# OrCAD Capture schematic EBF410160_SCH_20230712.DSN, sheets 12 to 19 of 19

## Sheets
12 16 MIPI CSI PORT: size A4; note: MIPI CSI PORT
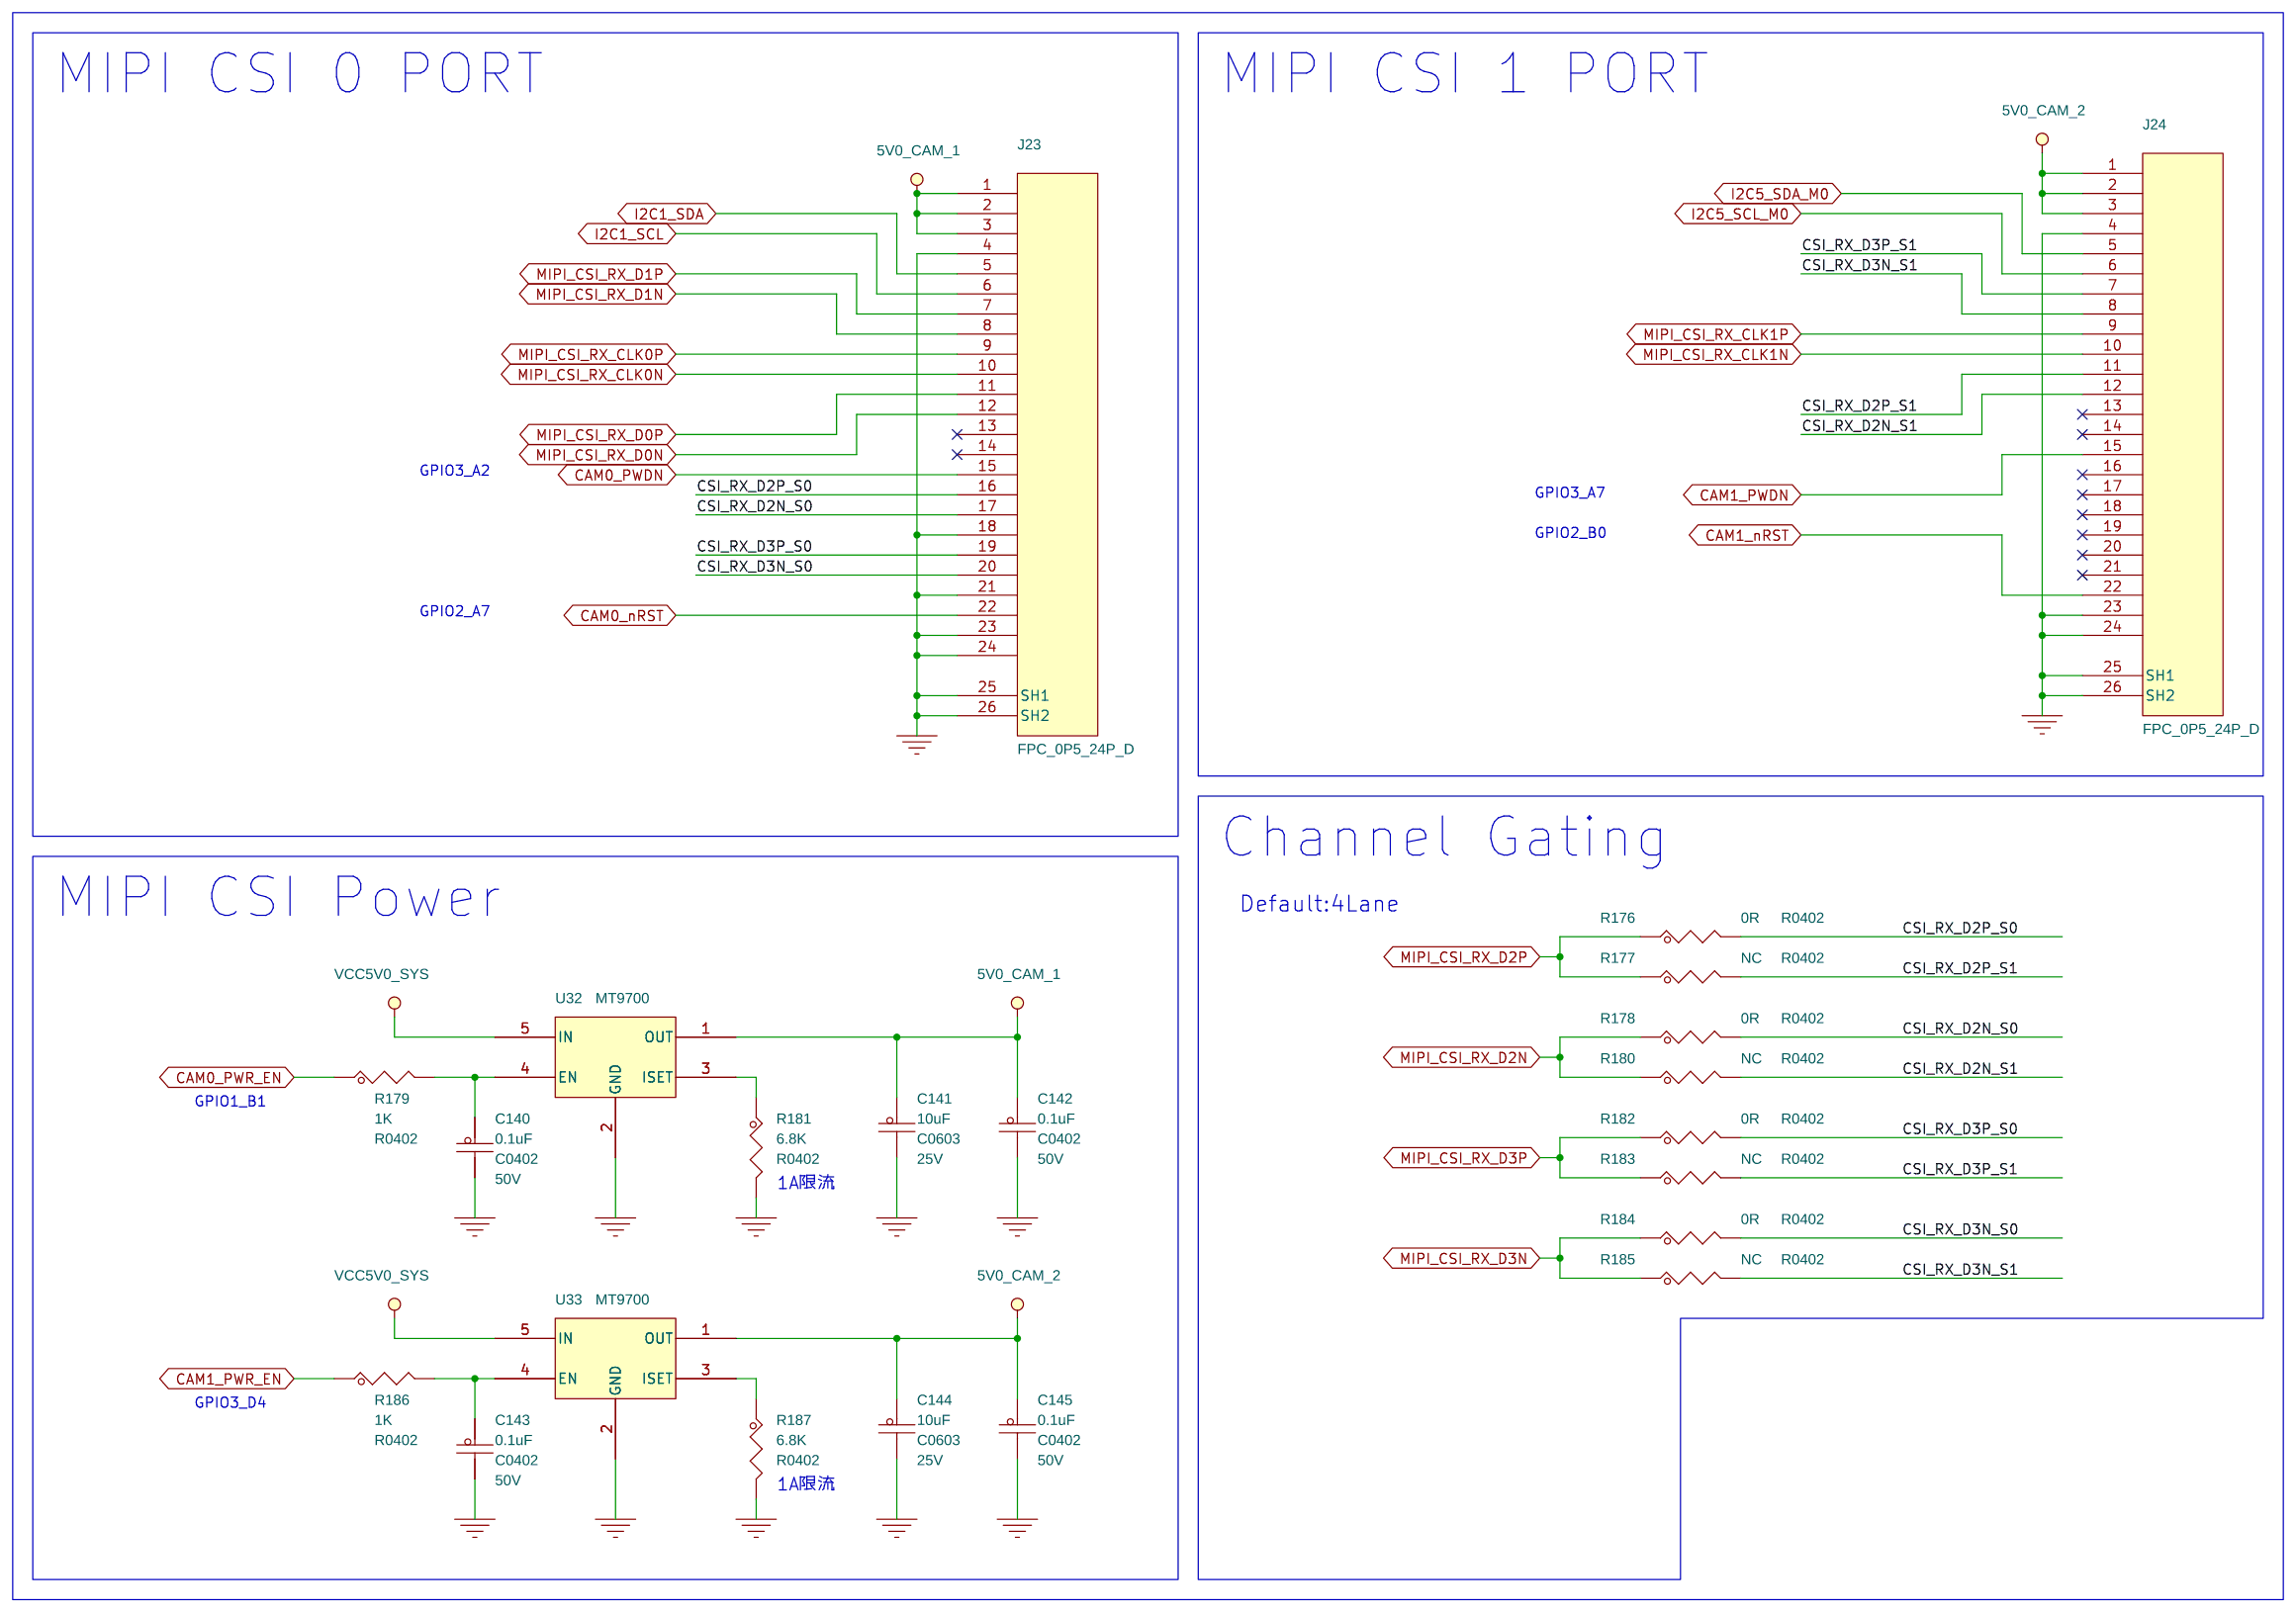
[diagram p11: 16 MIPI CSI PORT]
13 18 MINI PCIE_PORT: size A3; note: MINI PCIE PORT
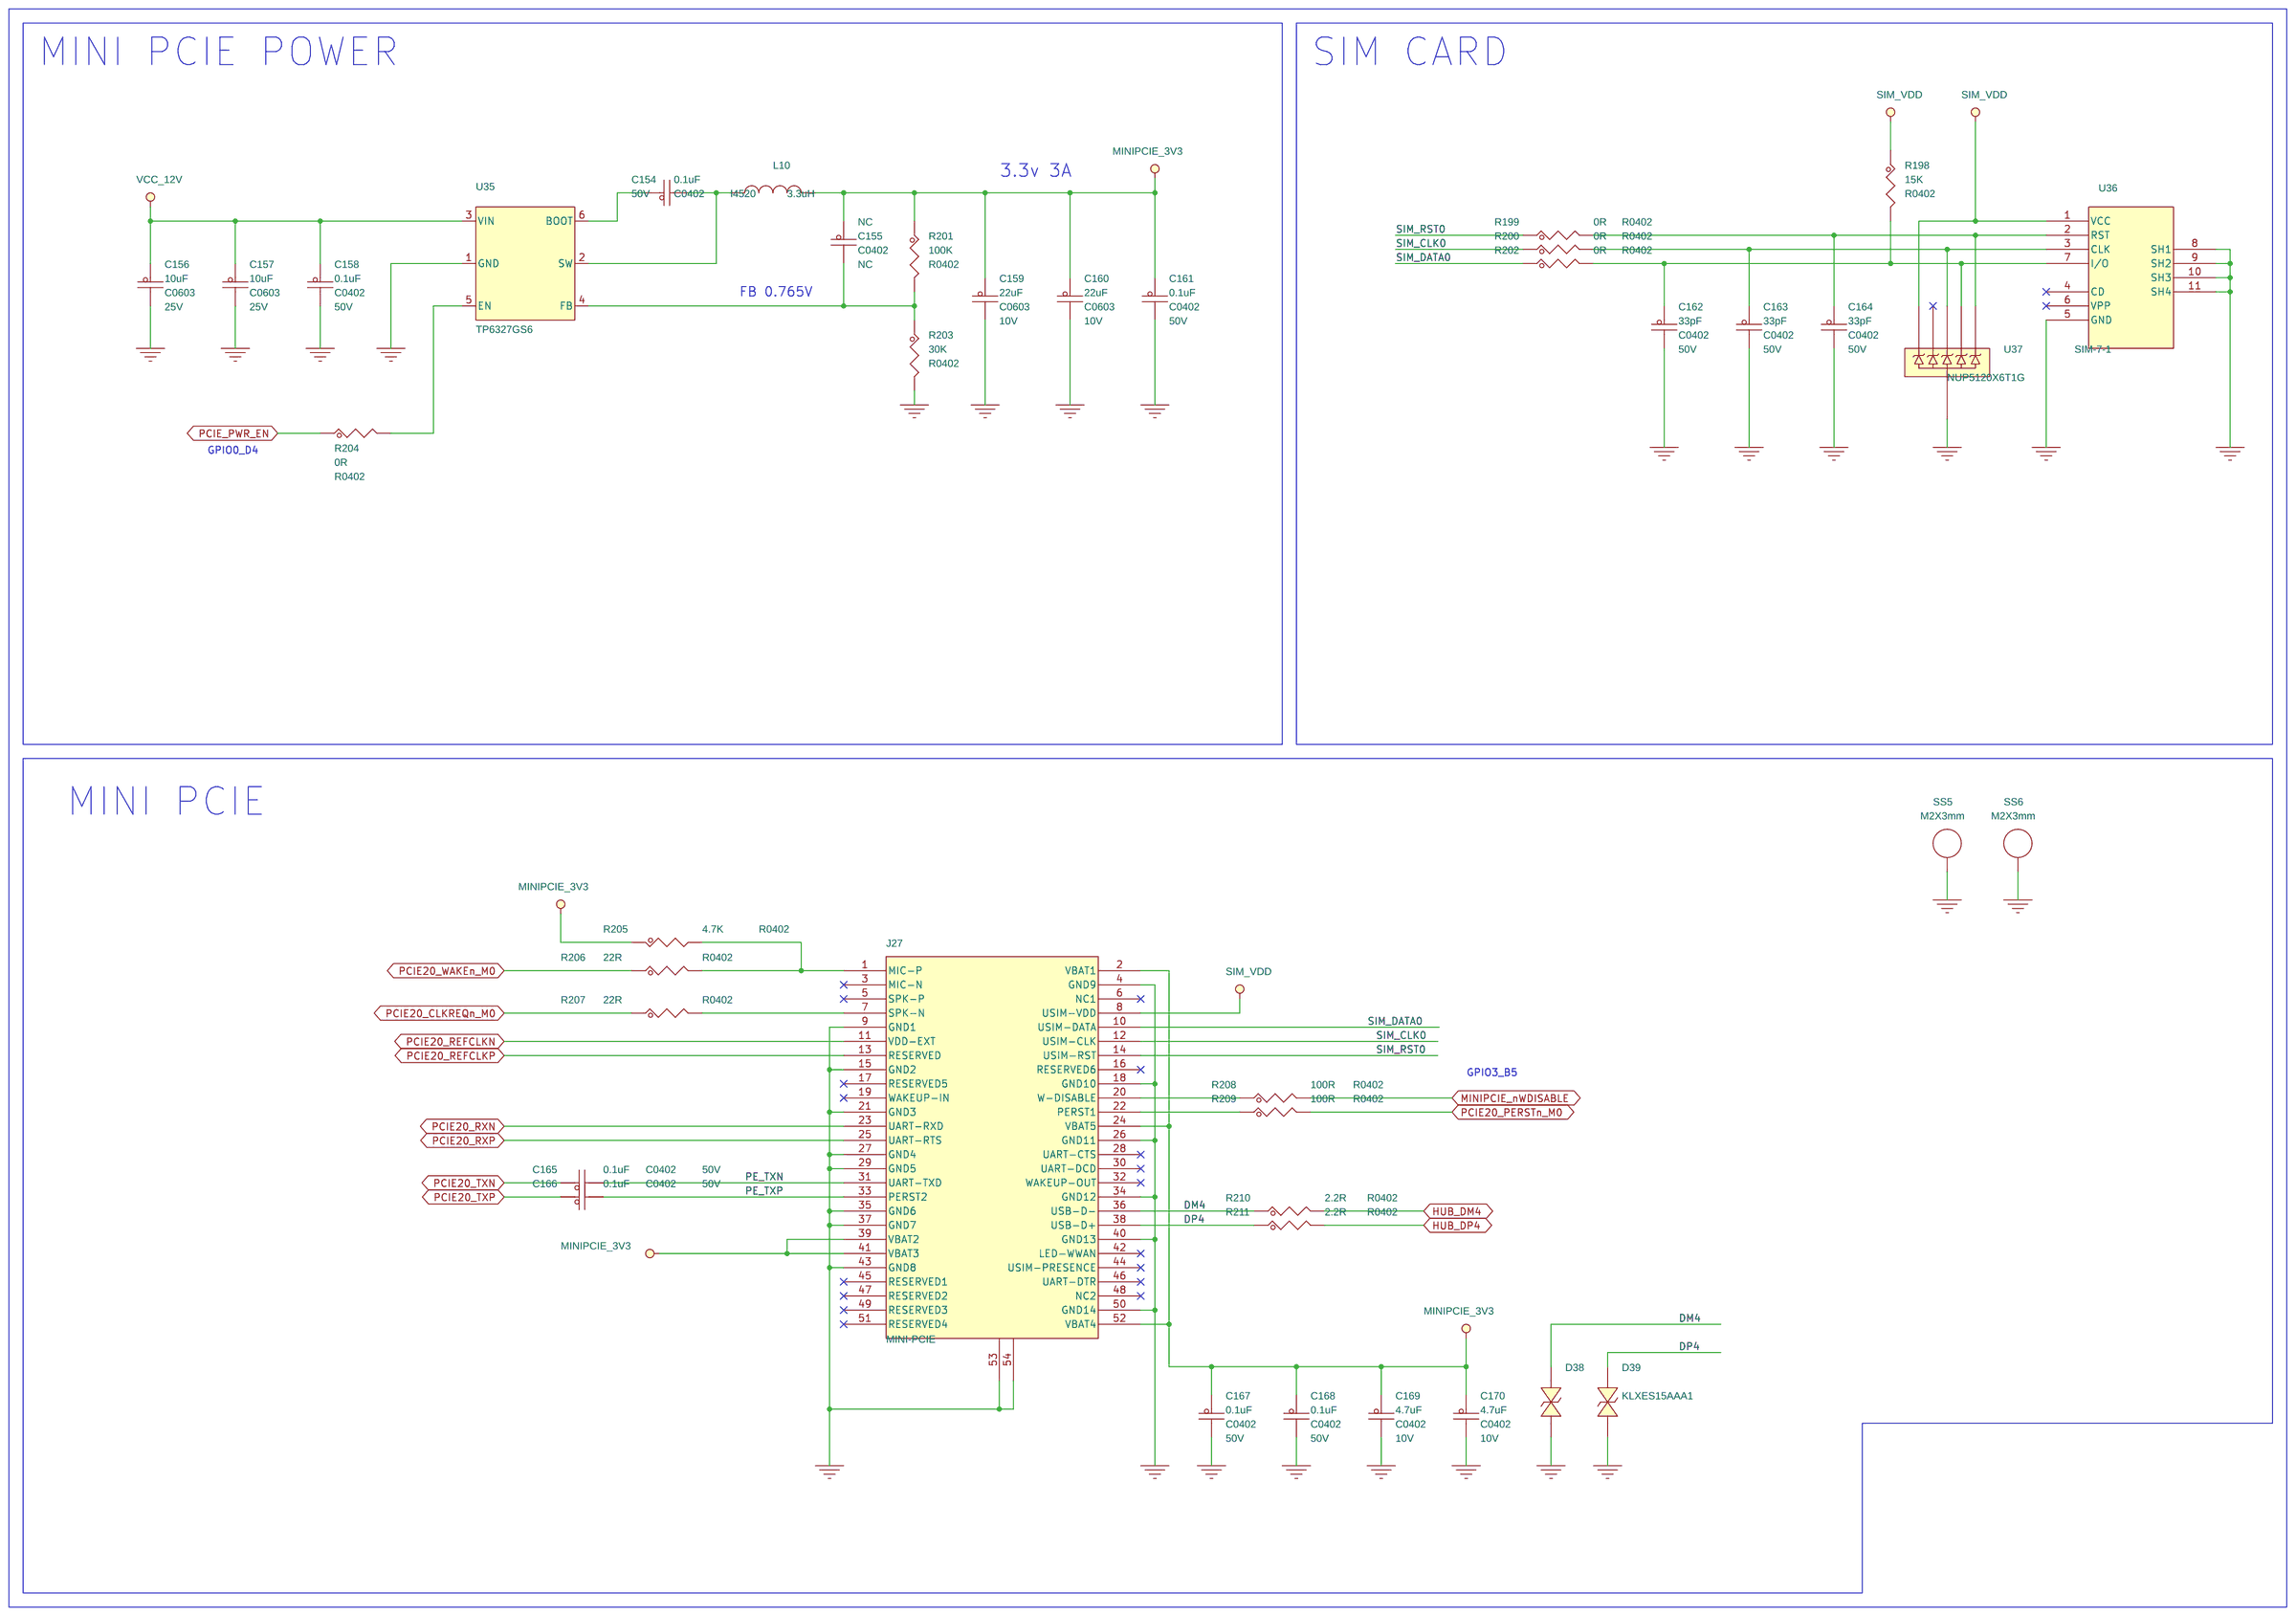
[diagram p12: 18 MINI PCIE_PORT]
14 19 AUDIO PORT: size A4; note: AUDIO PORT
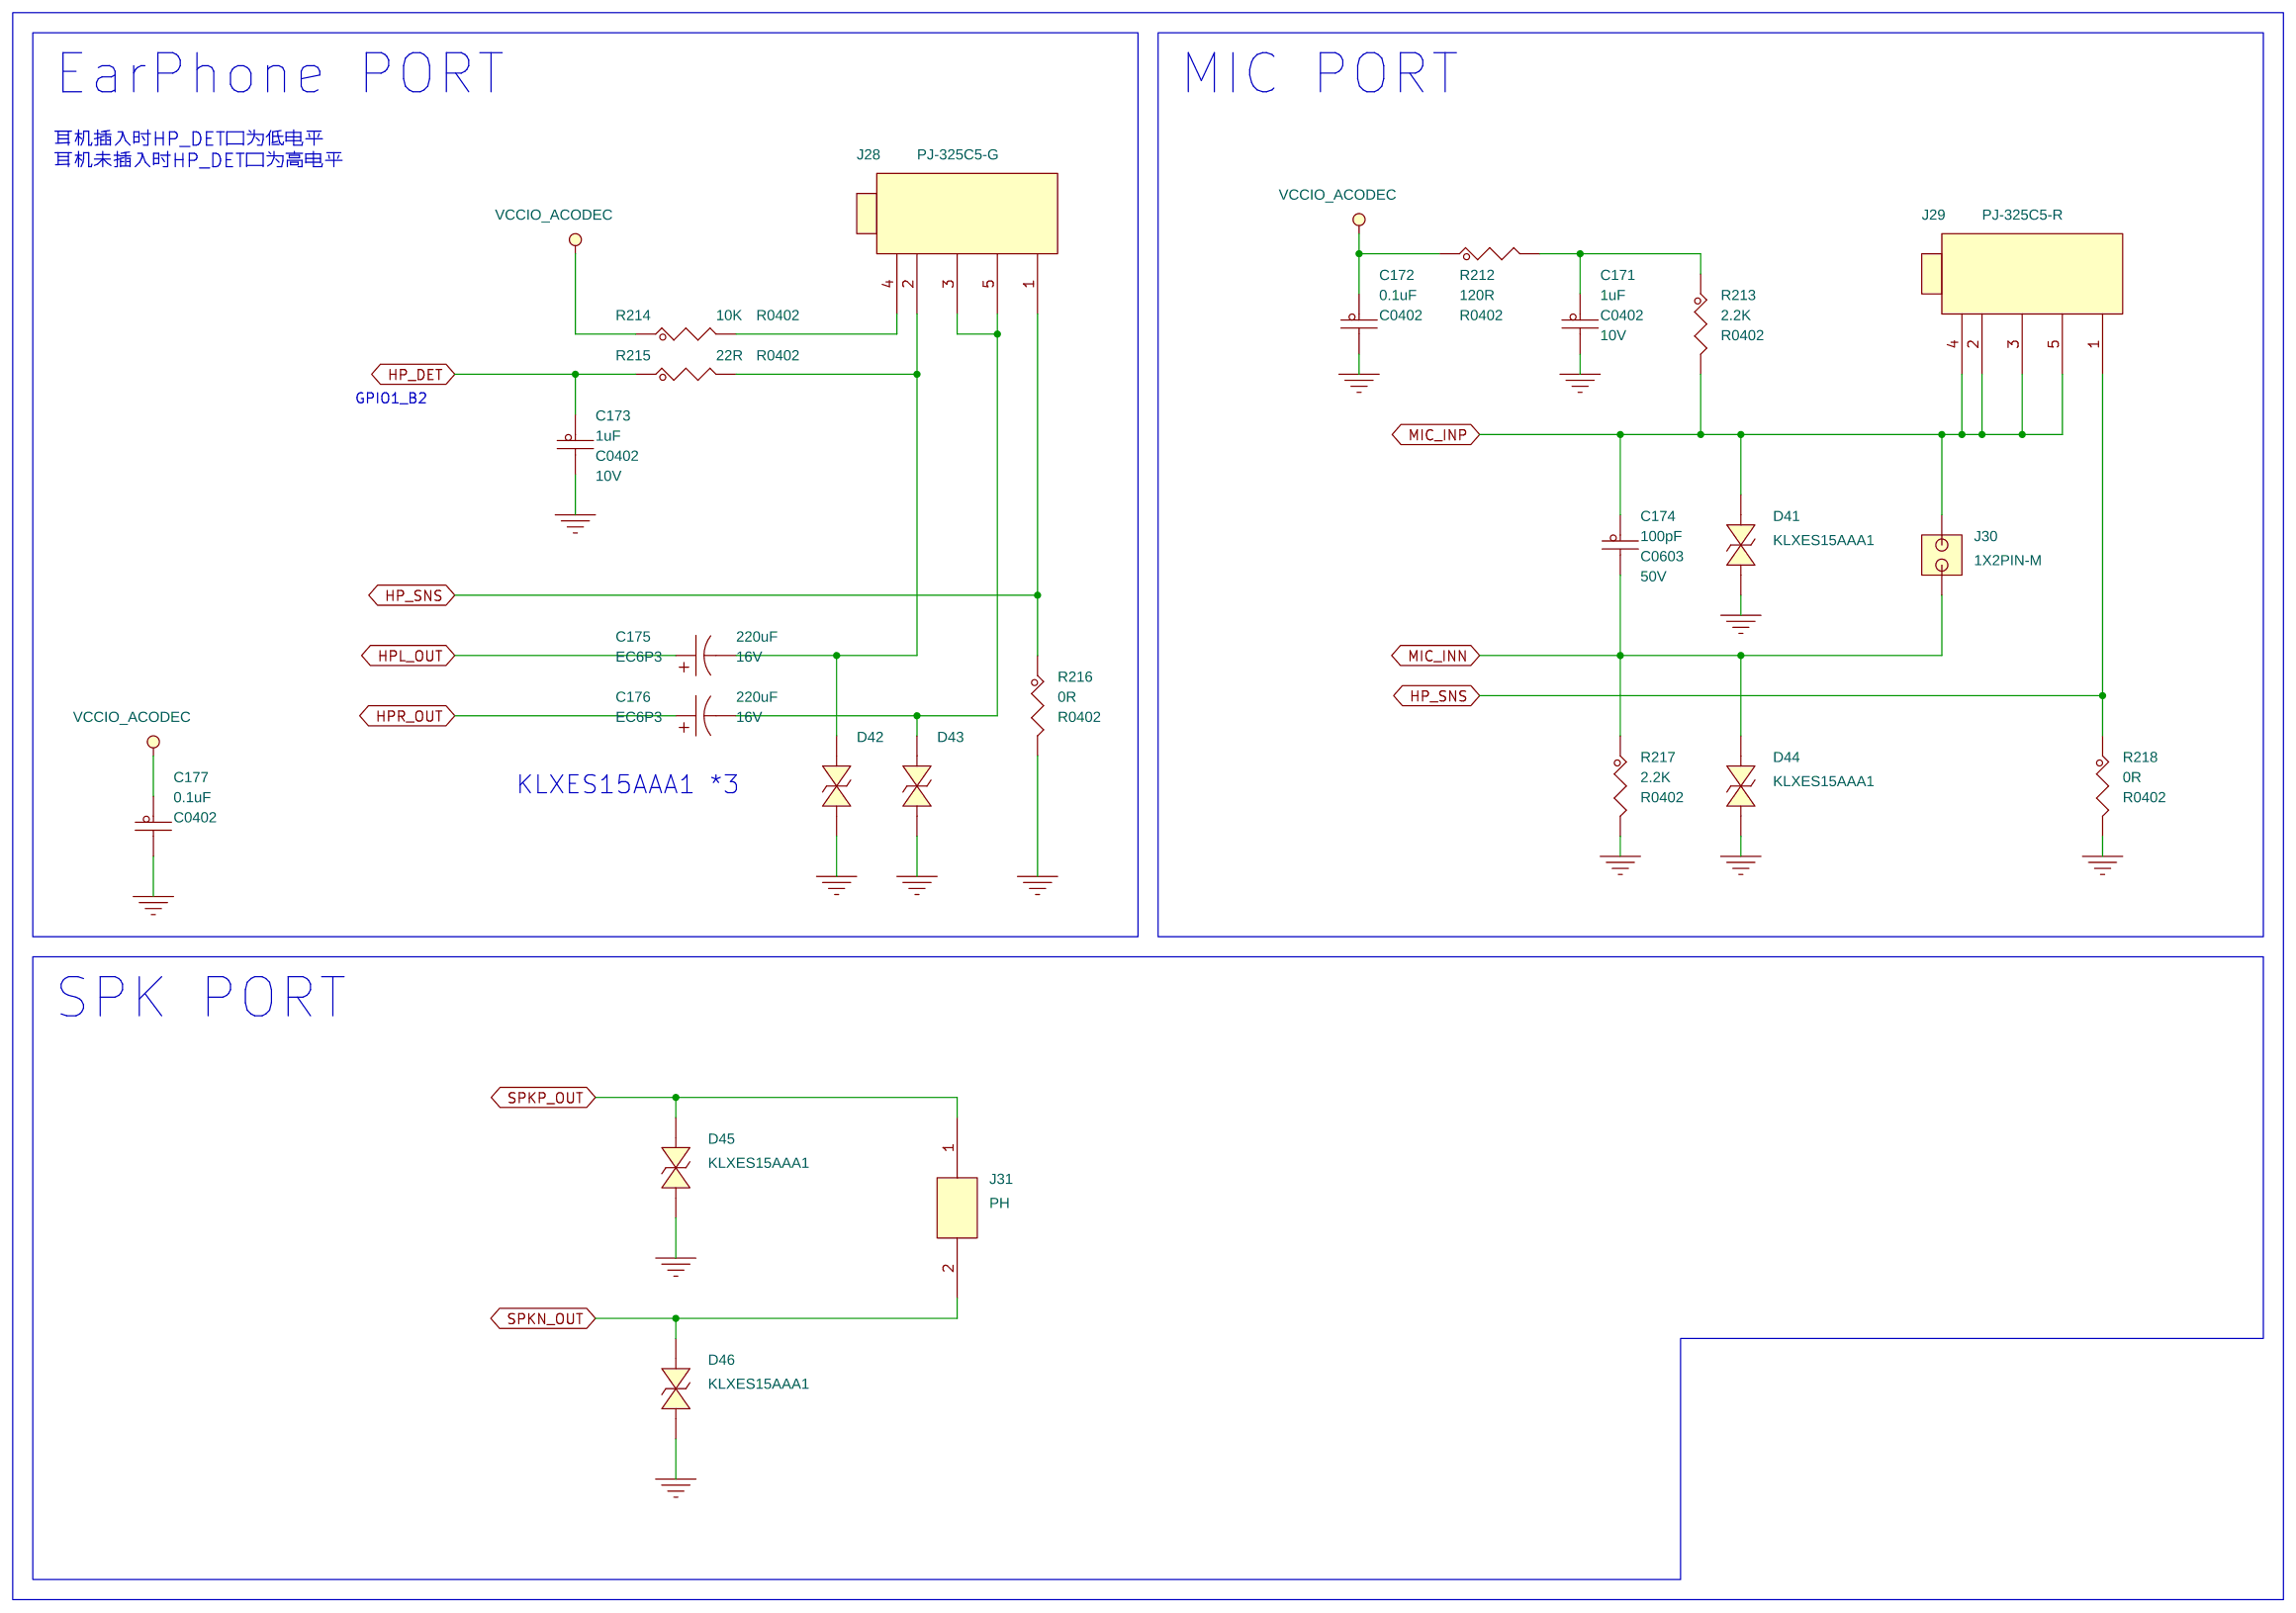
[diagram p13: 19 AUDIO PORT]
15 08 SD/RTC/RS232: size A3; note: SD/RTC/RS232
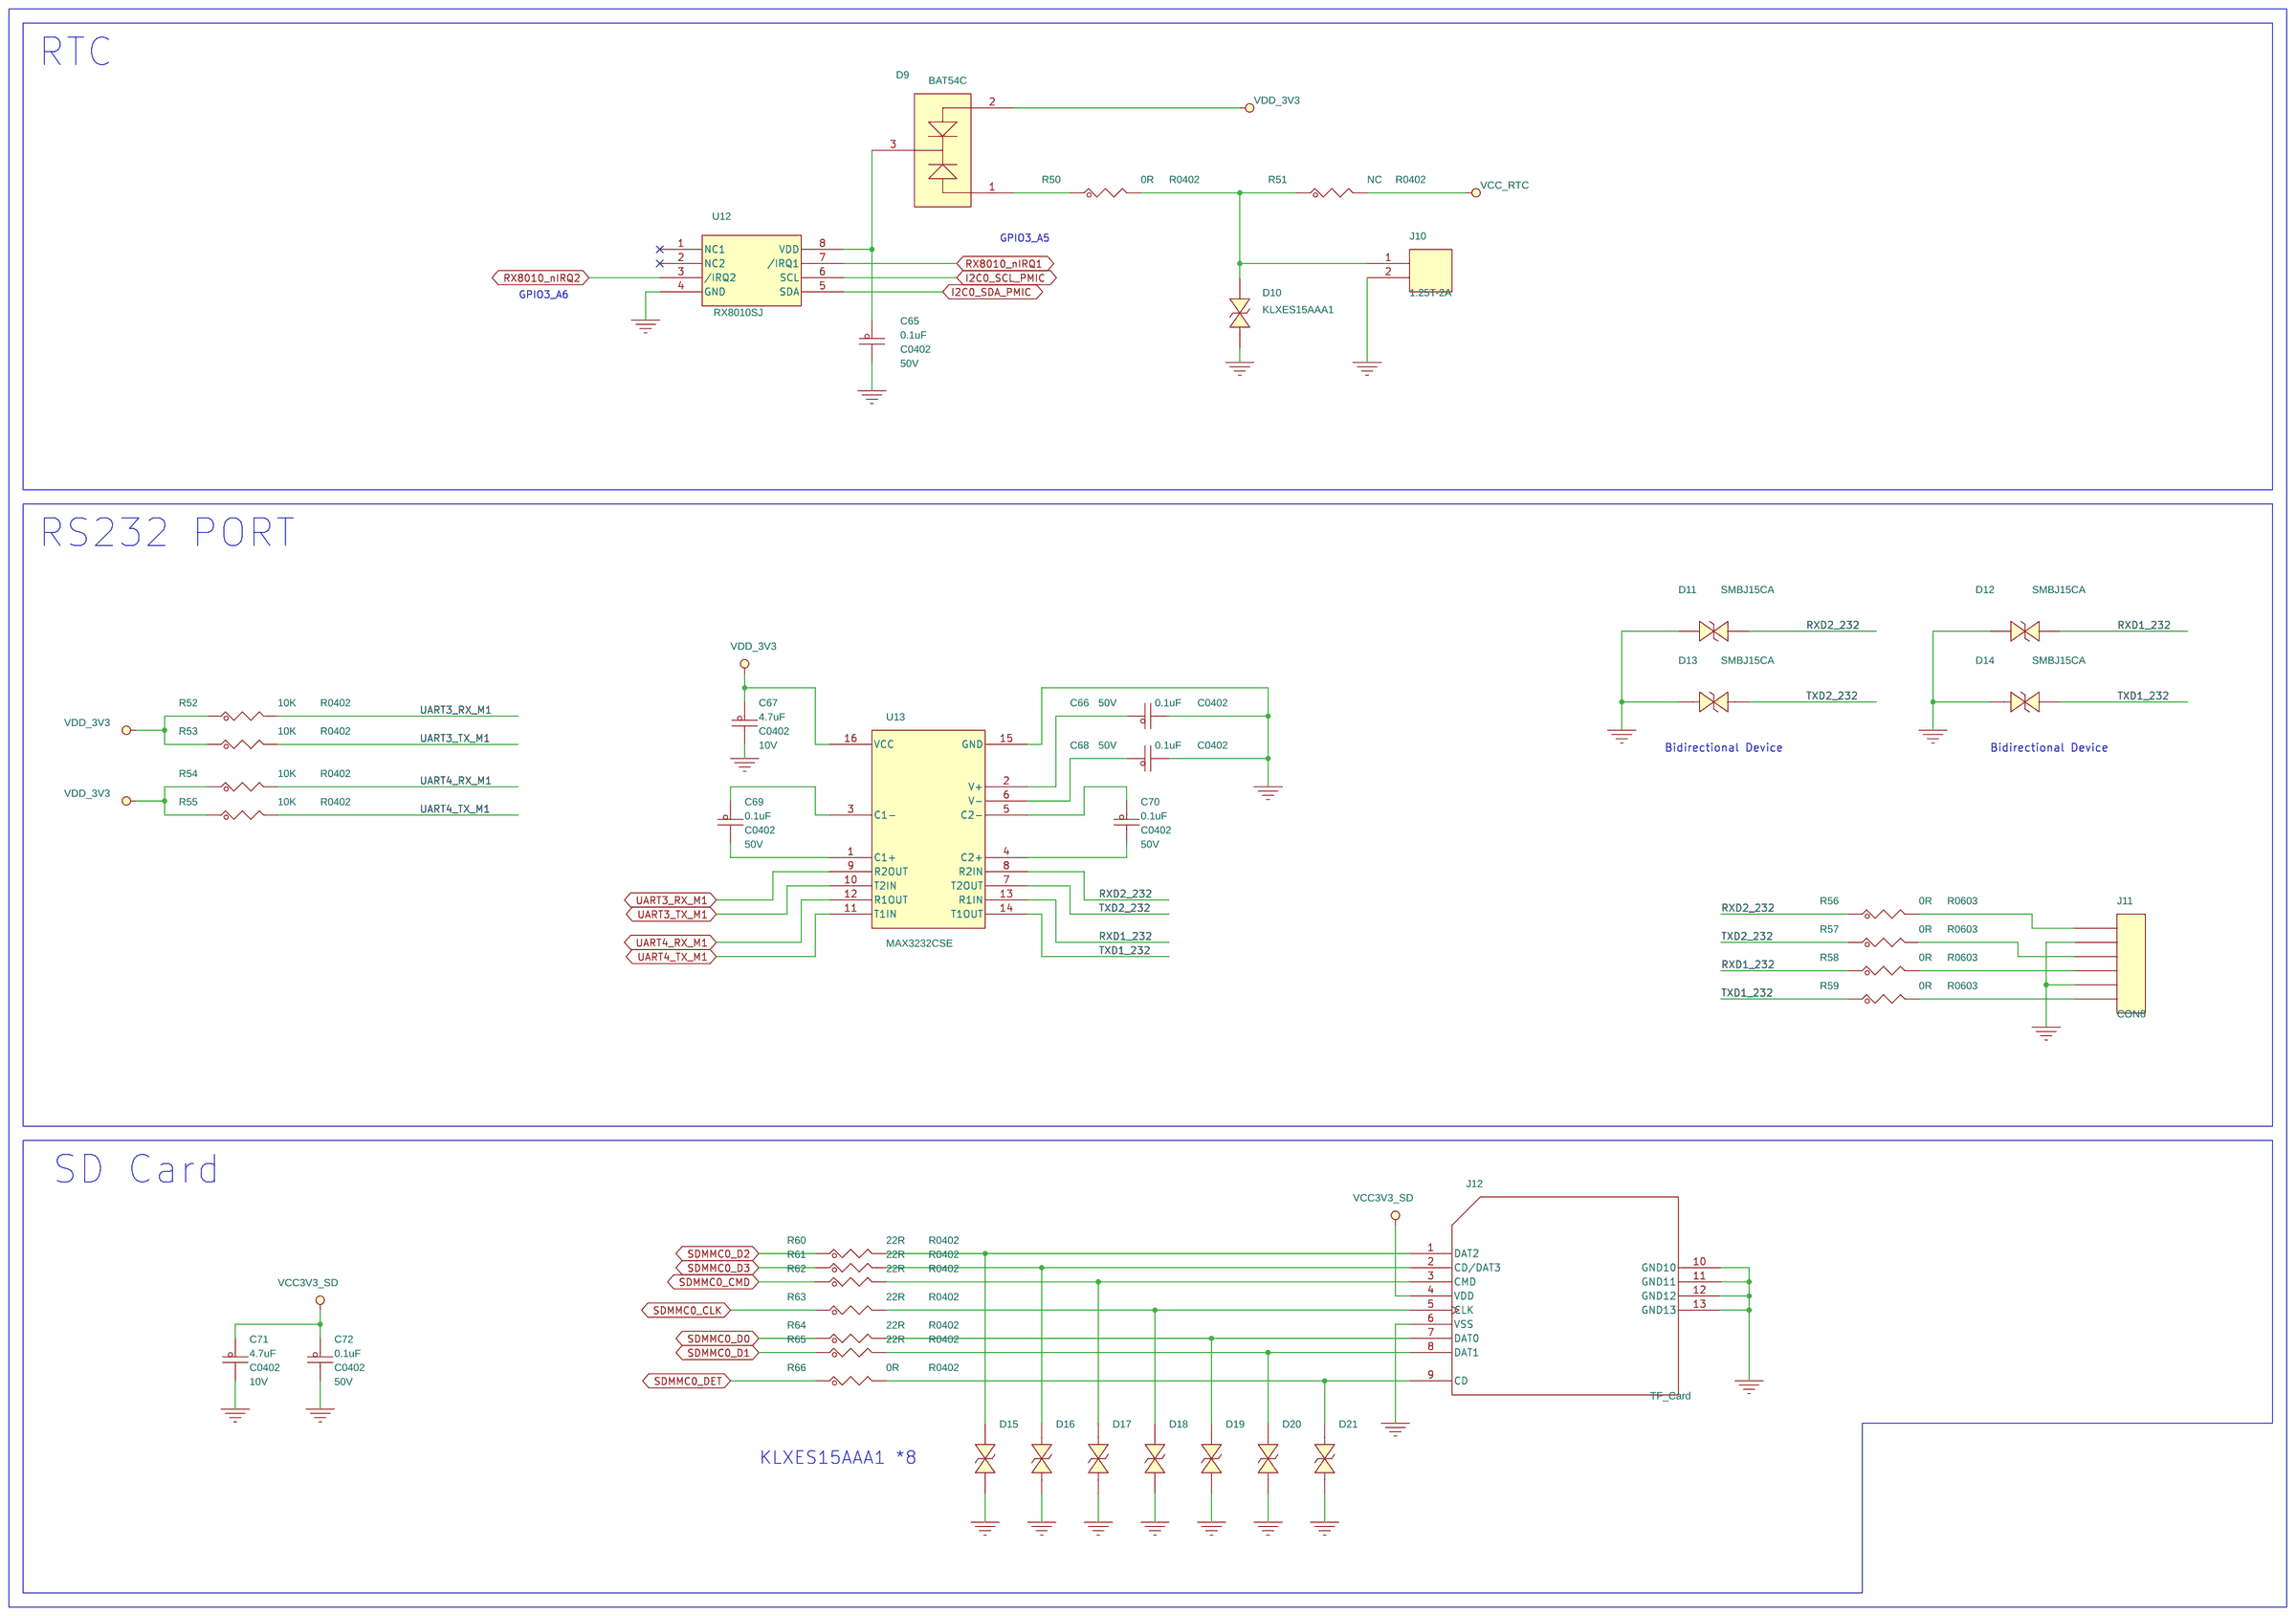
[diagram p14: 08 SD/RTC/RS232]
16 10 I2C/UART PORT: size A4; note: 40P  GPIO
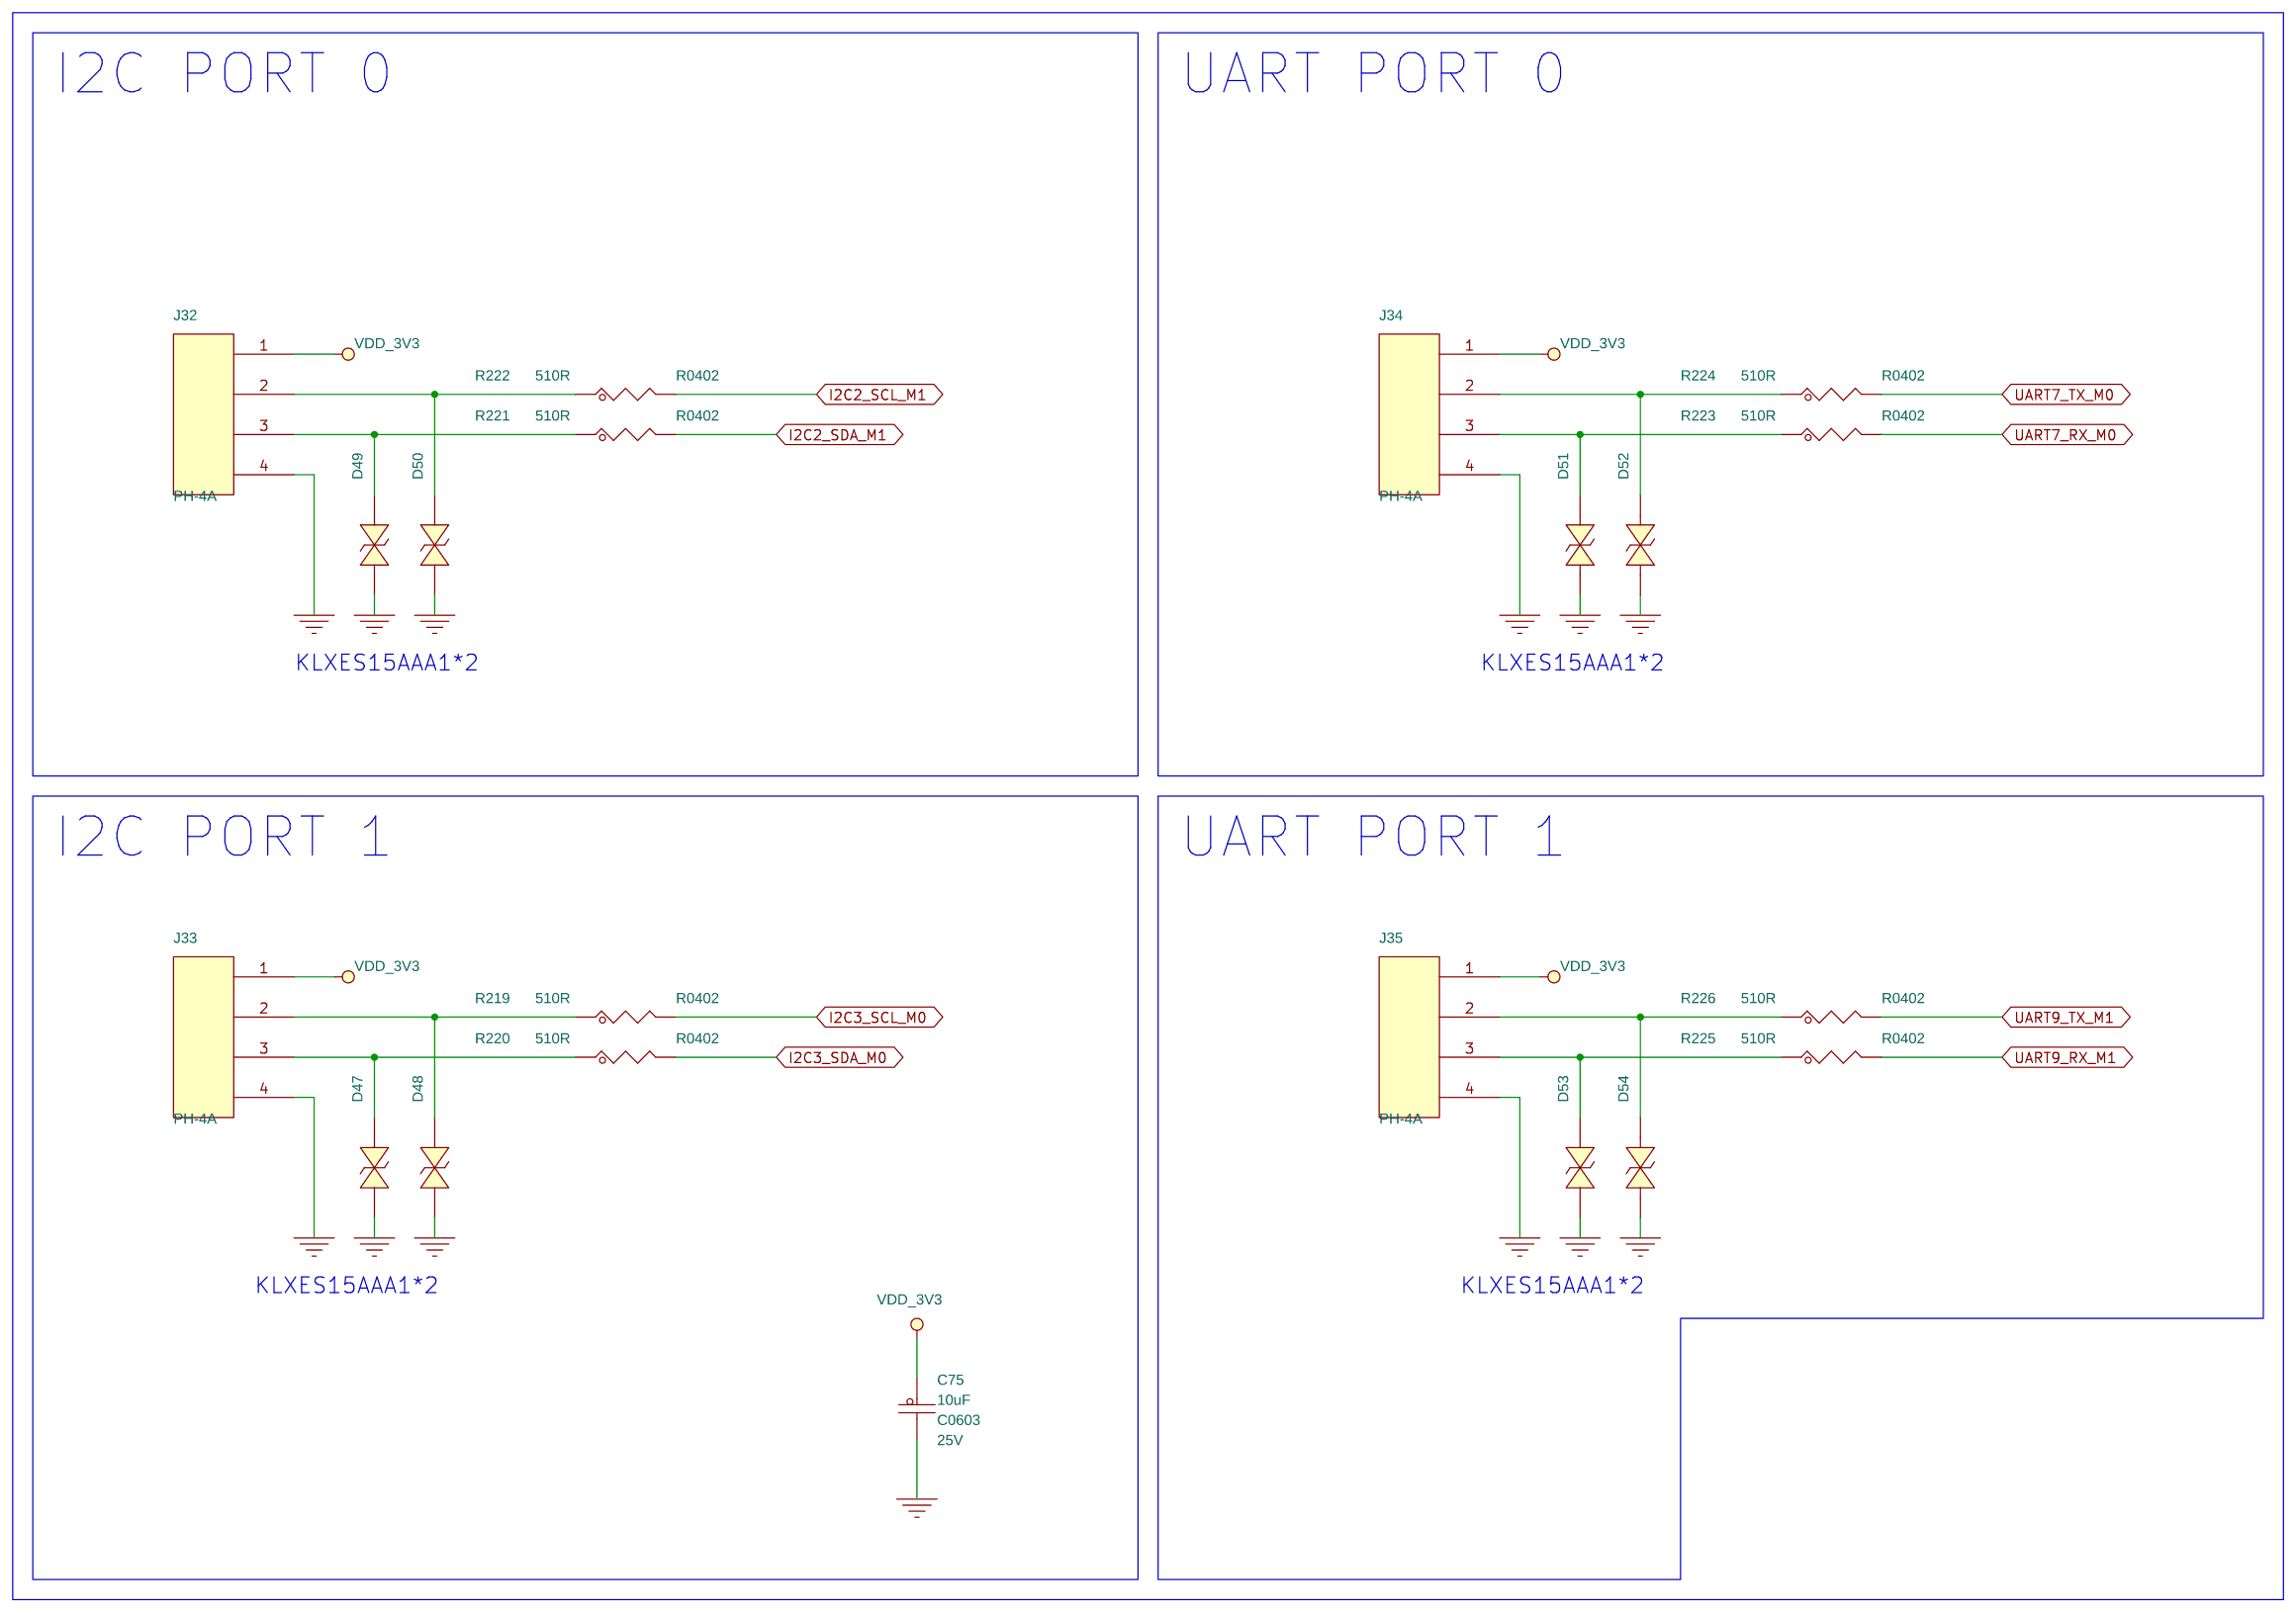
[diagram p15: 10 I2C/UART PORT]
17 04 DC IN/POWER/FAN: size A3; note: DC IN/POWER/FAN
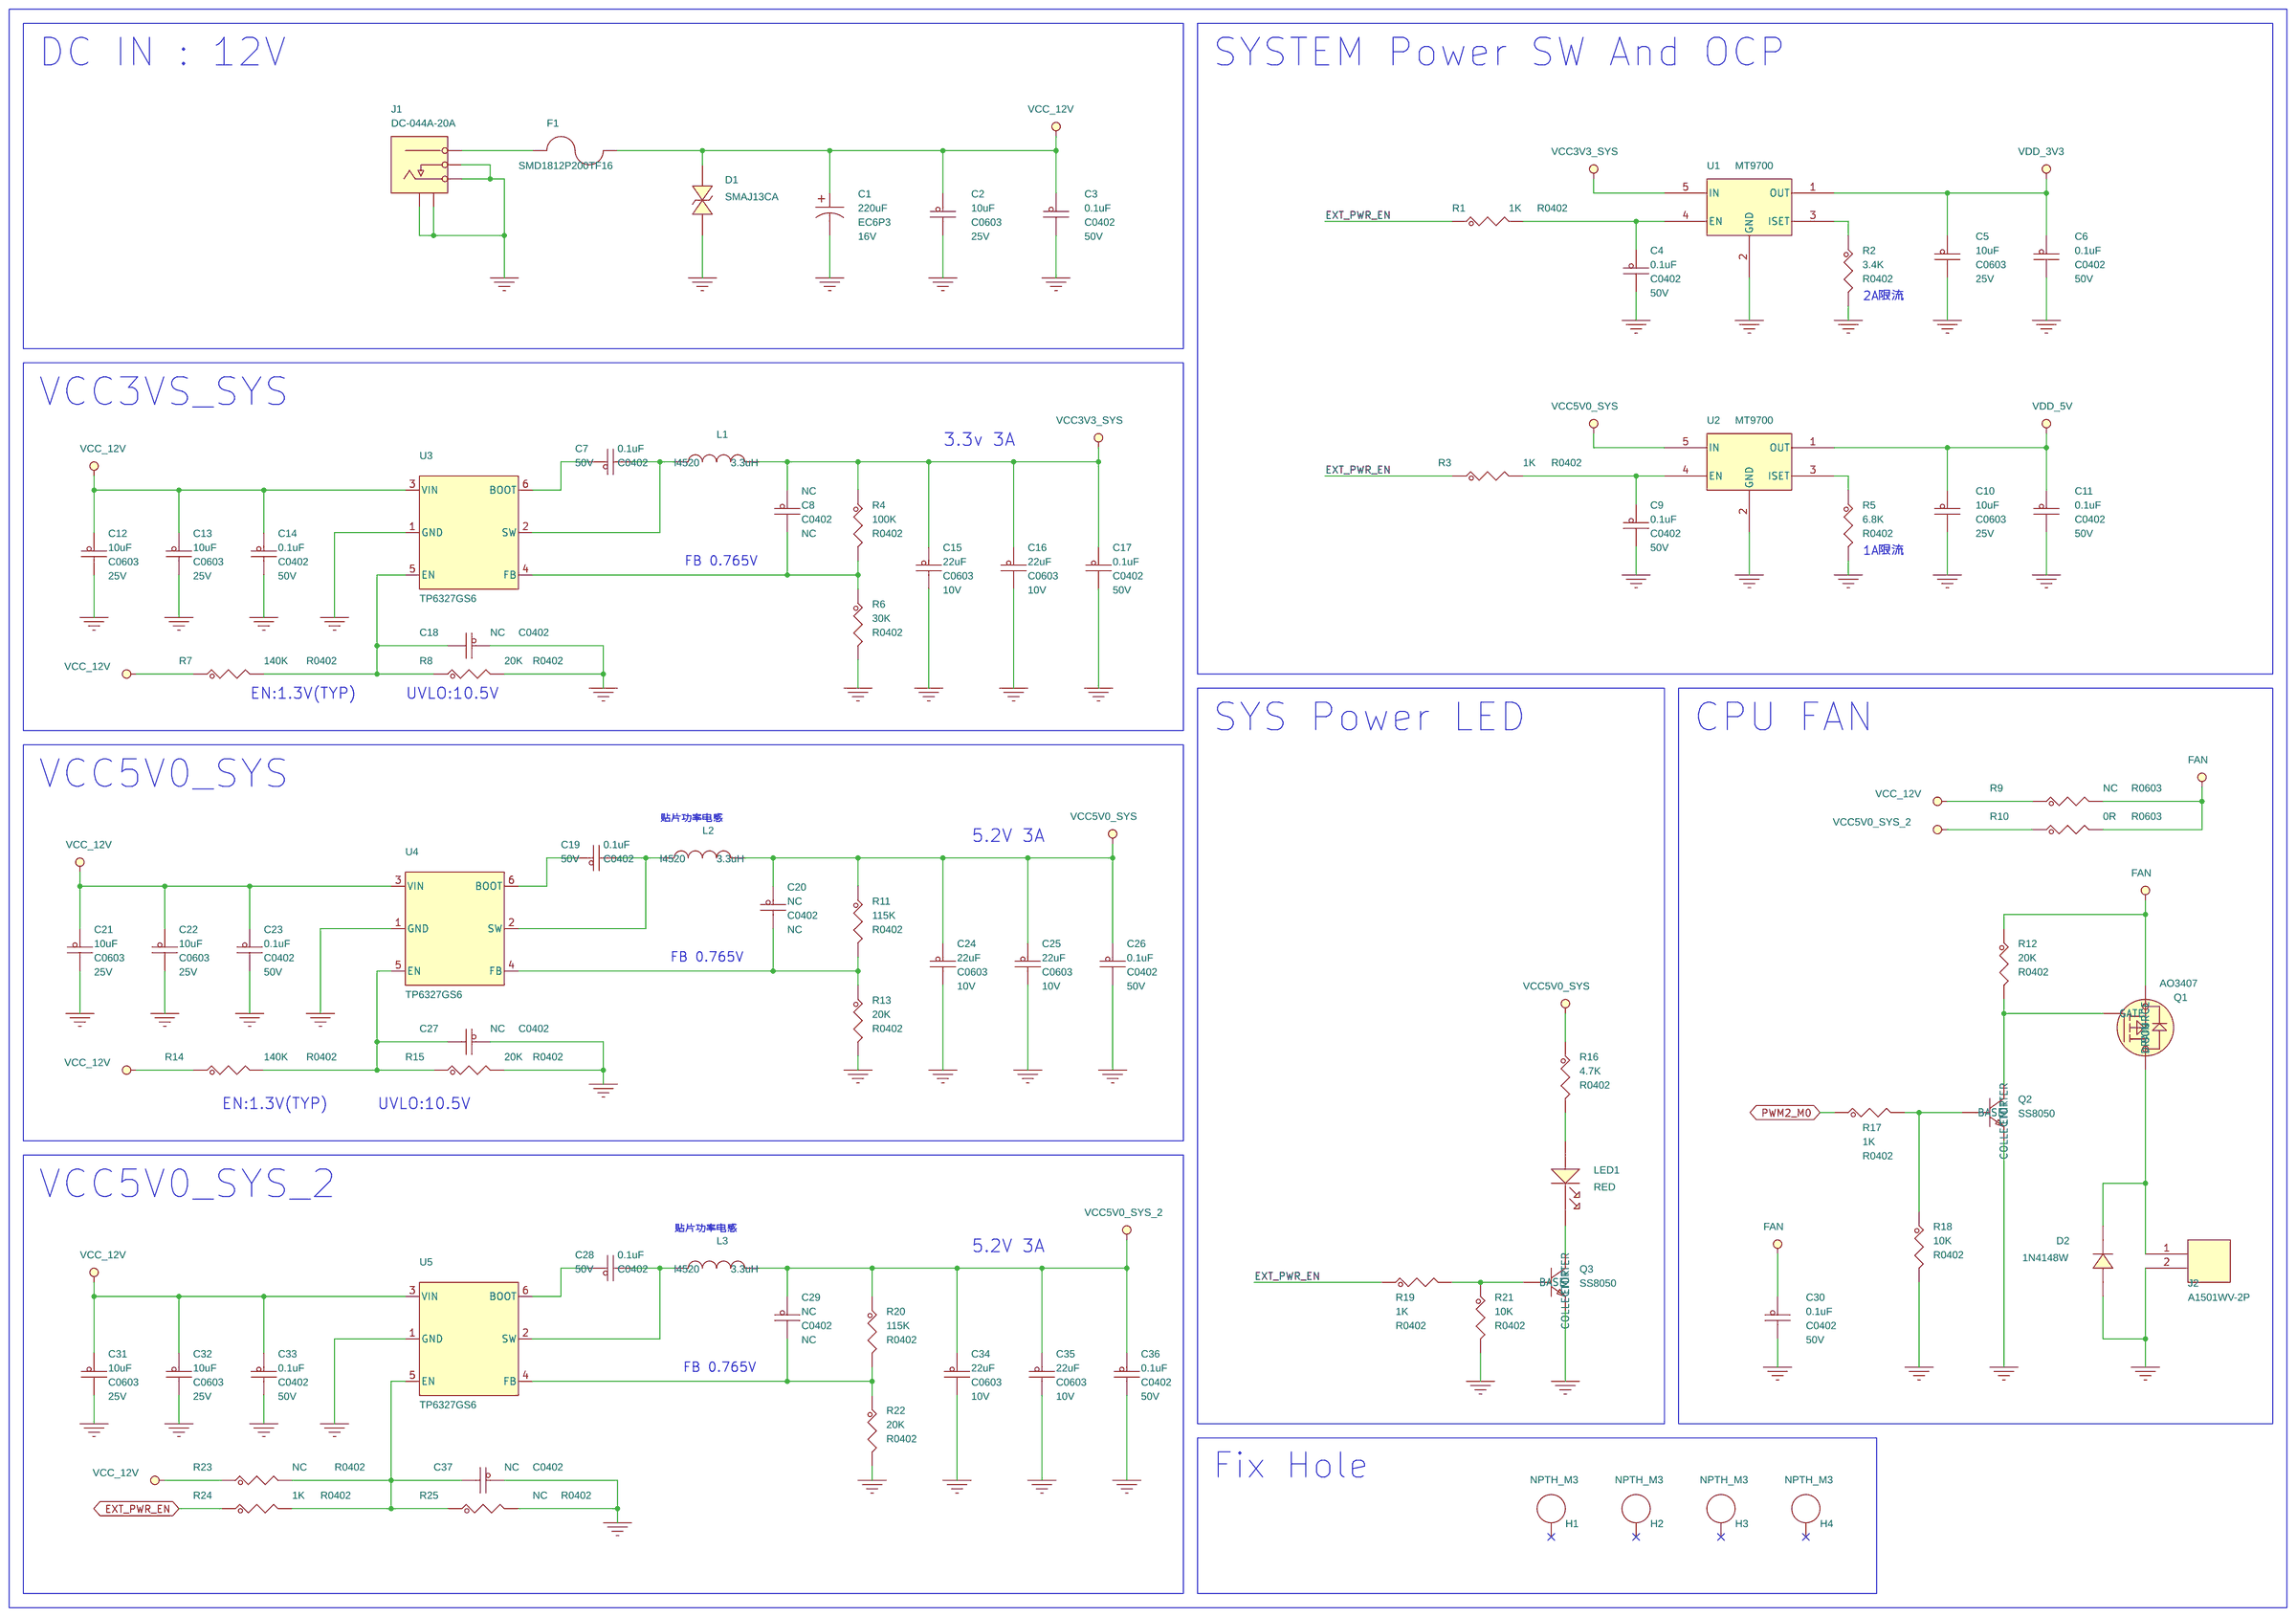
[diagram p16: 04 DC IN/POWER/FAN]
18 17 eDP_1.3/TP_PORT: size A4; note: eDP1.3/TP_PORT
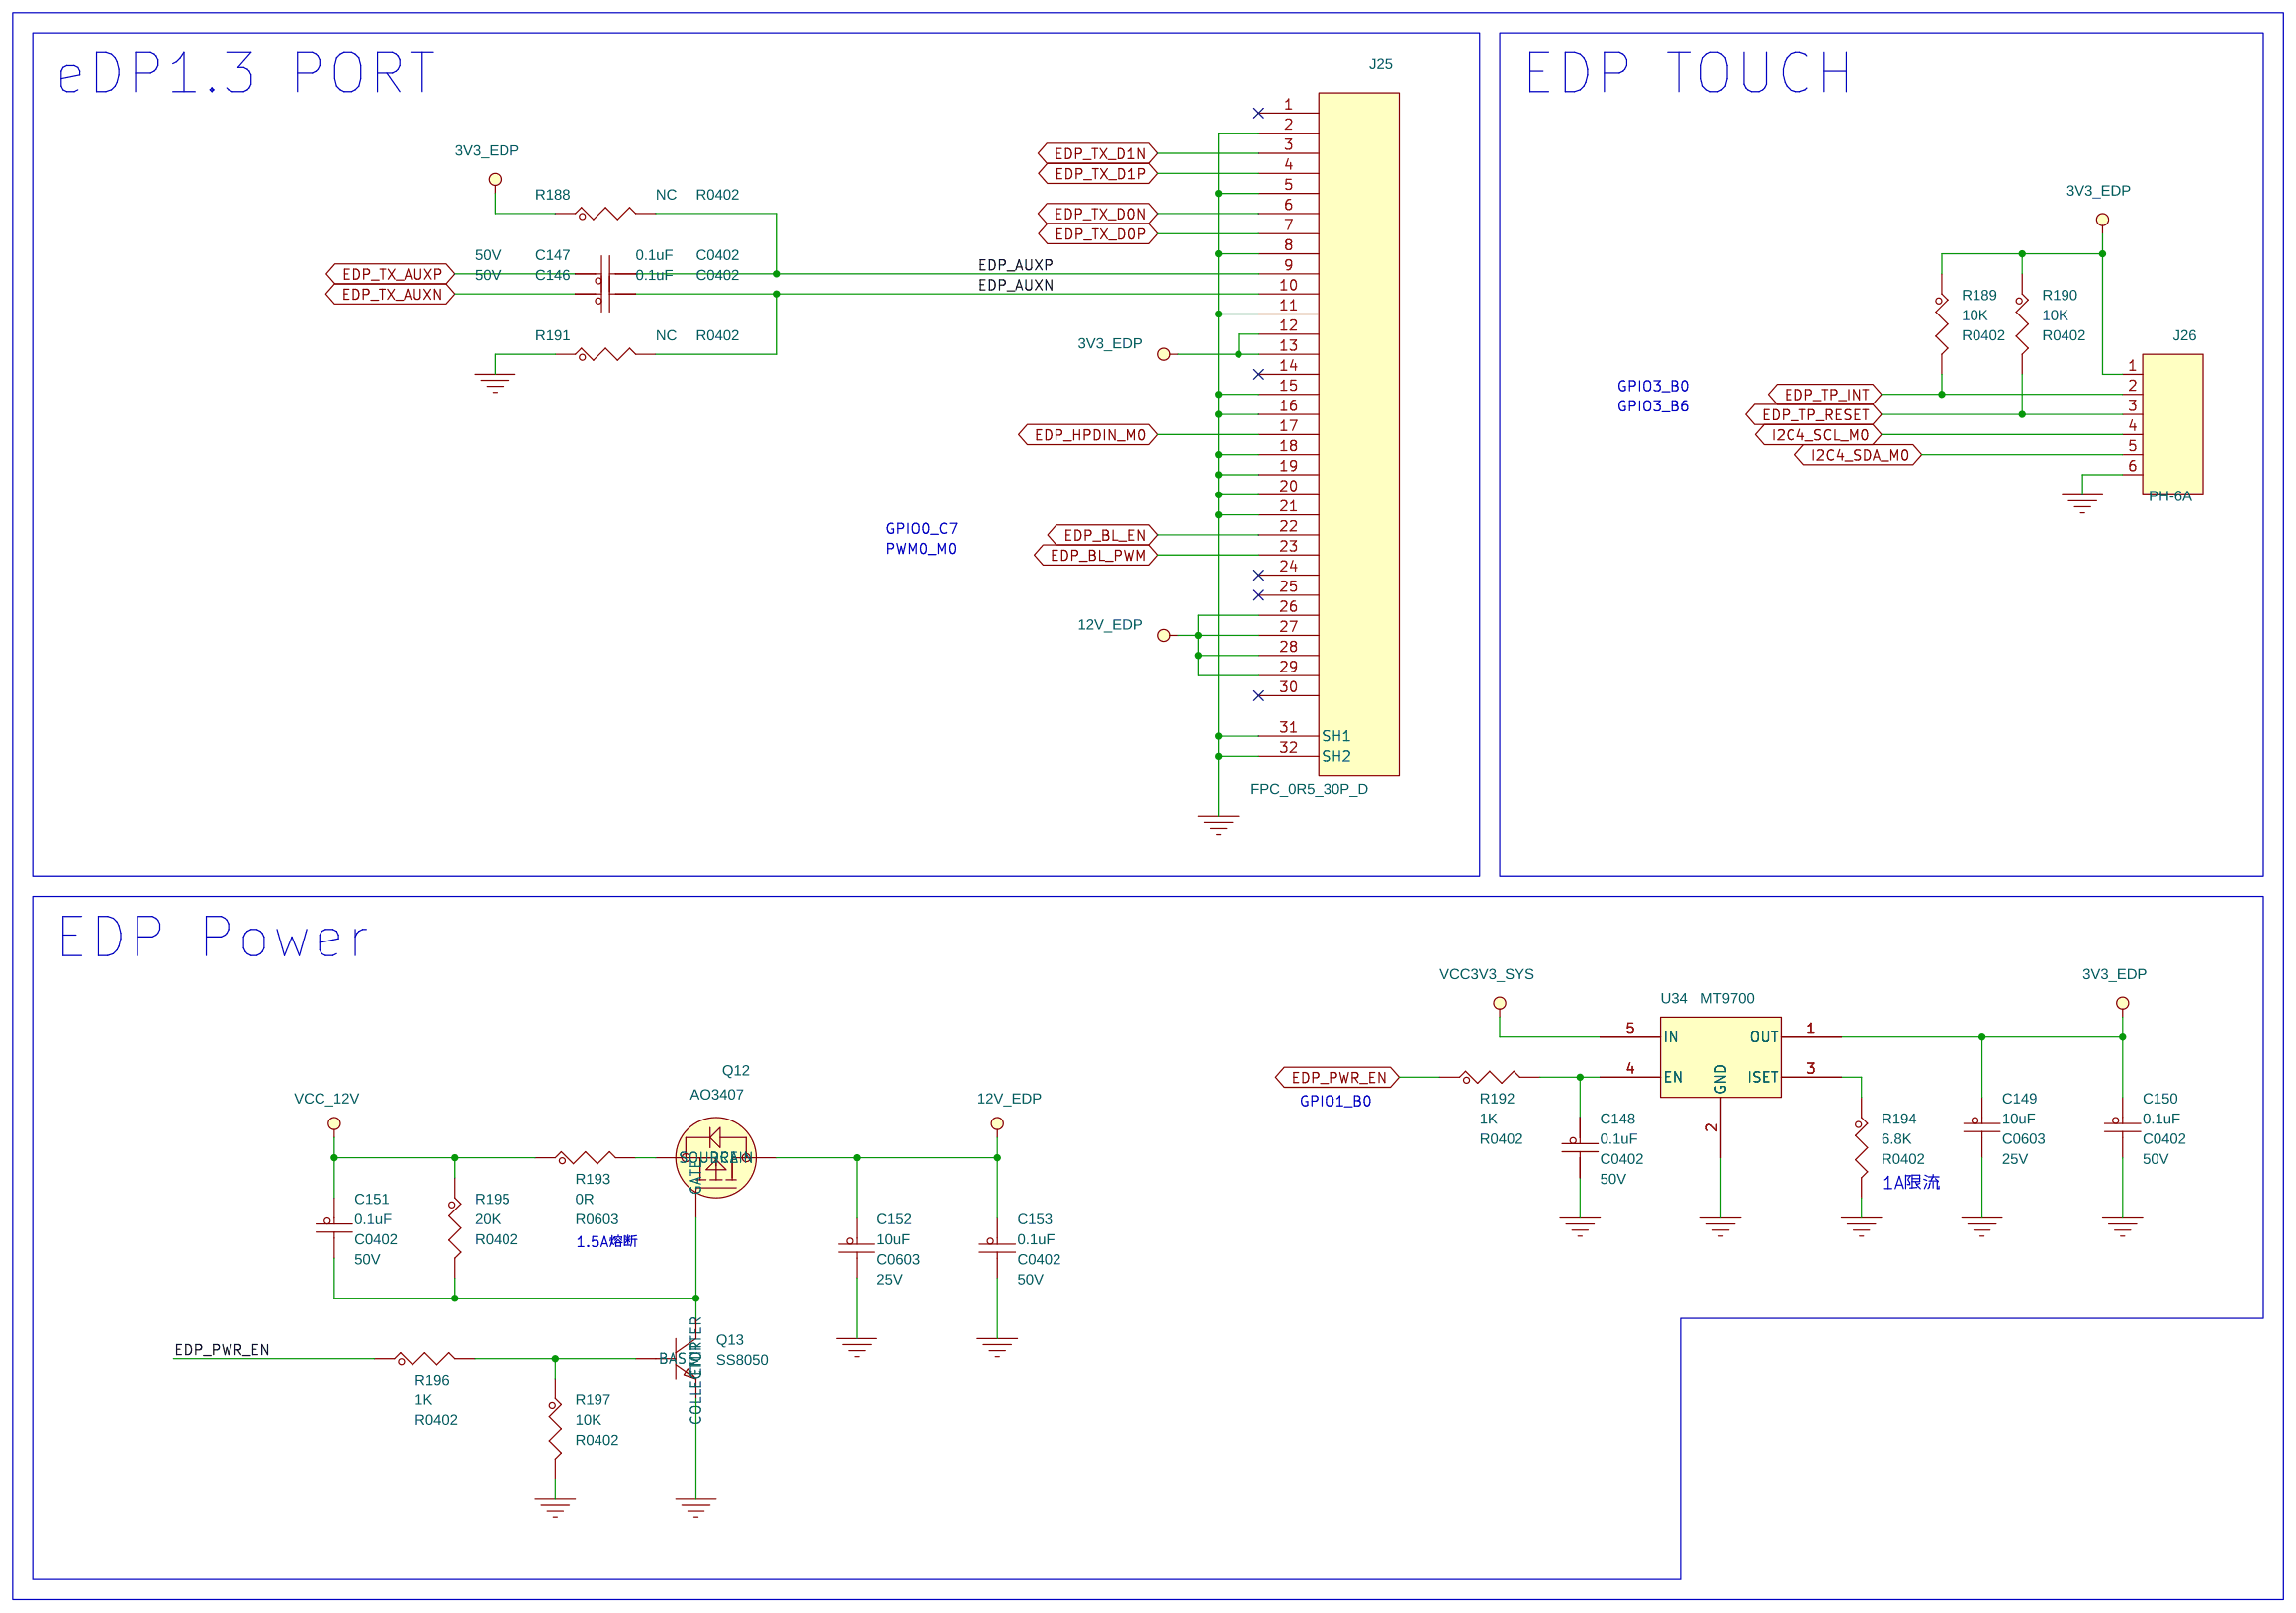
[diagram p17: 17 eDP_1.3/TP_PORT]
19 07 Button/FLASH/IR/DEBUG/LED: size A3; note: Button/FLASH/IR/DEBUG/LED
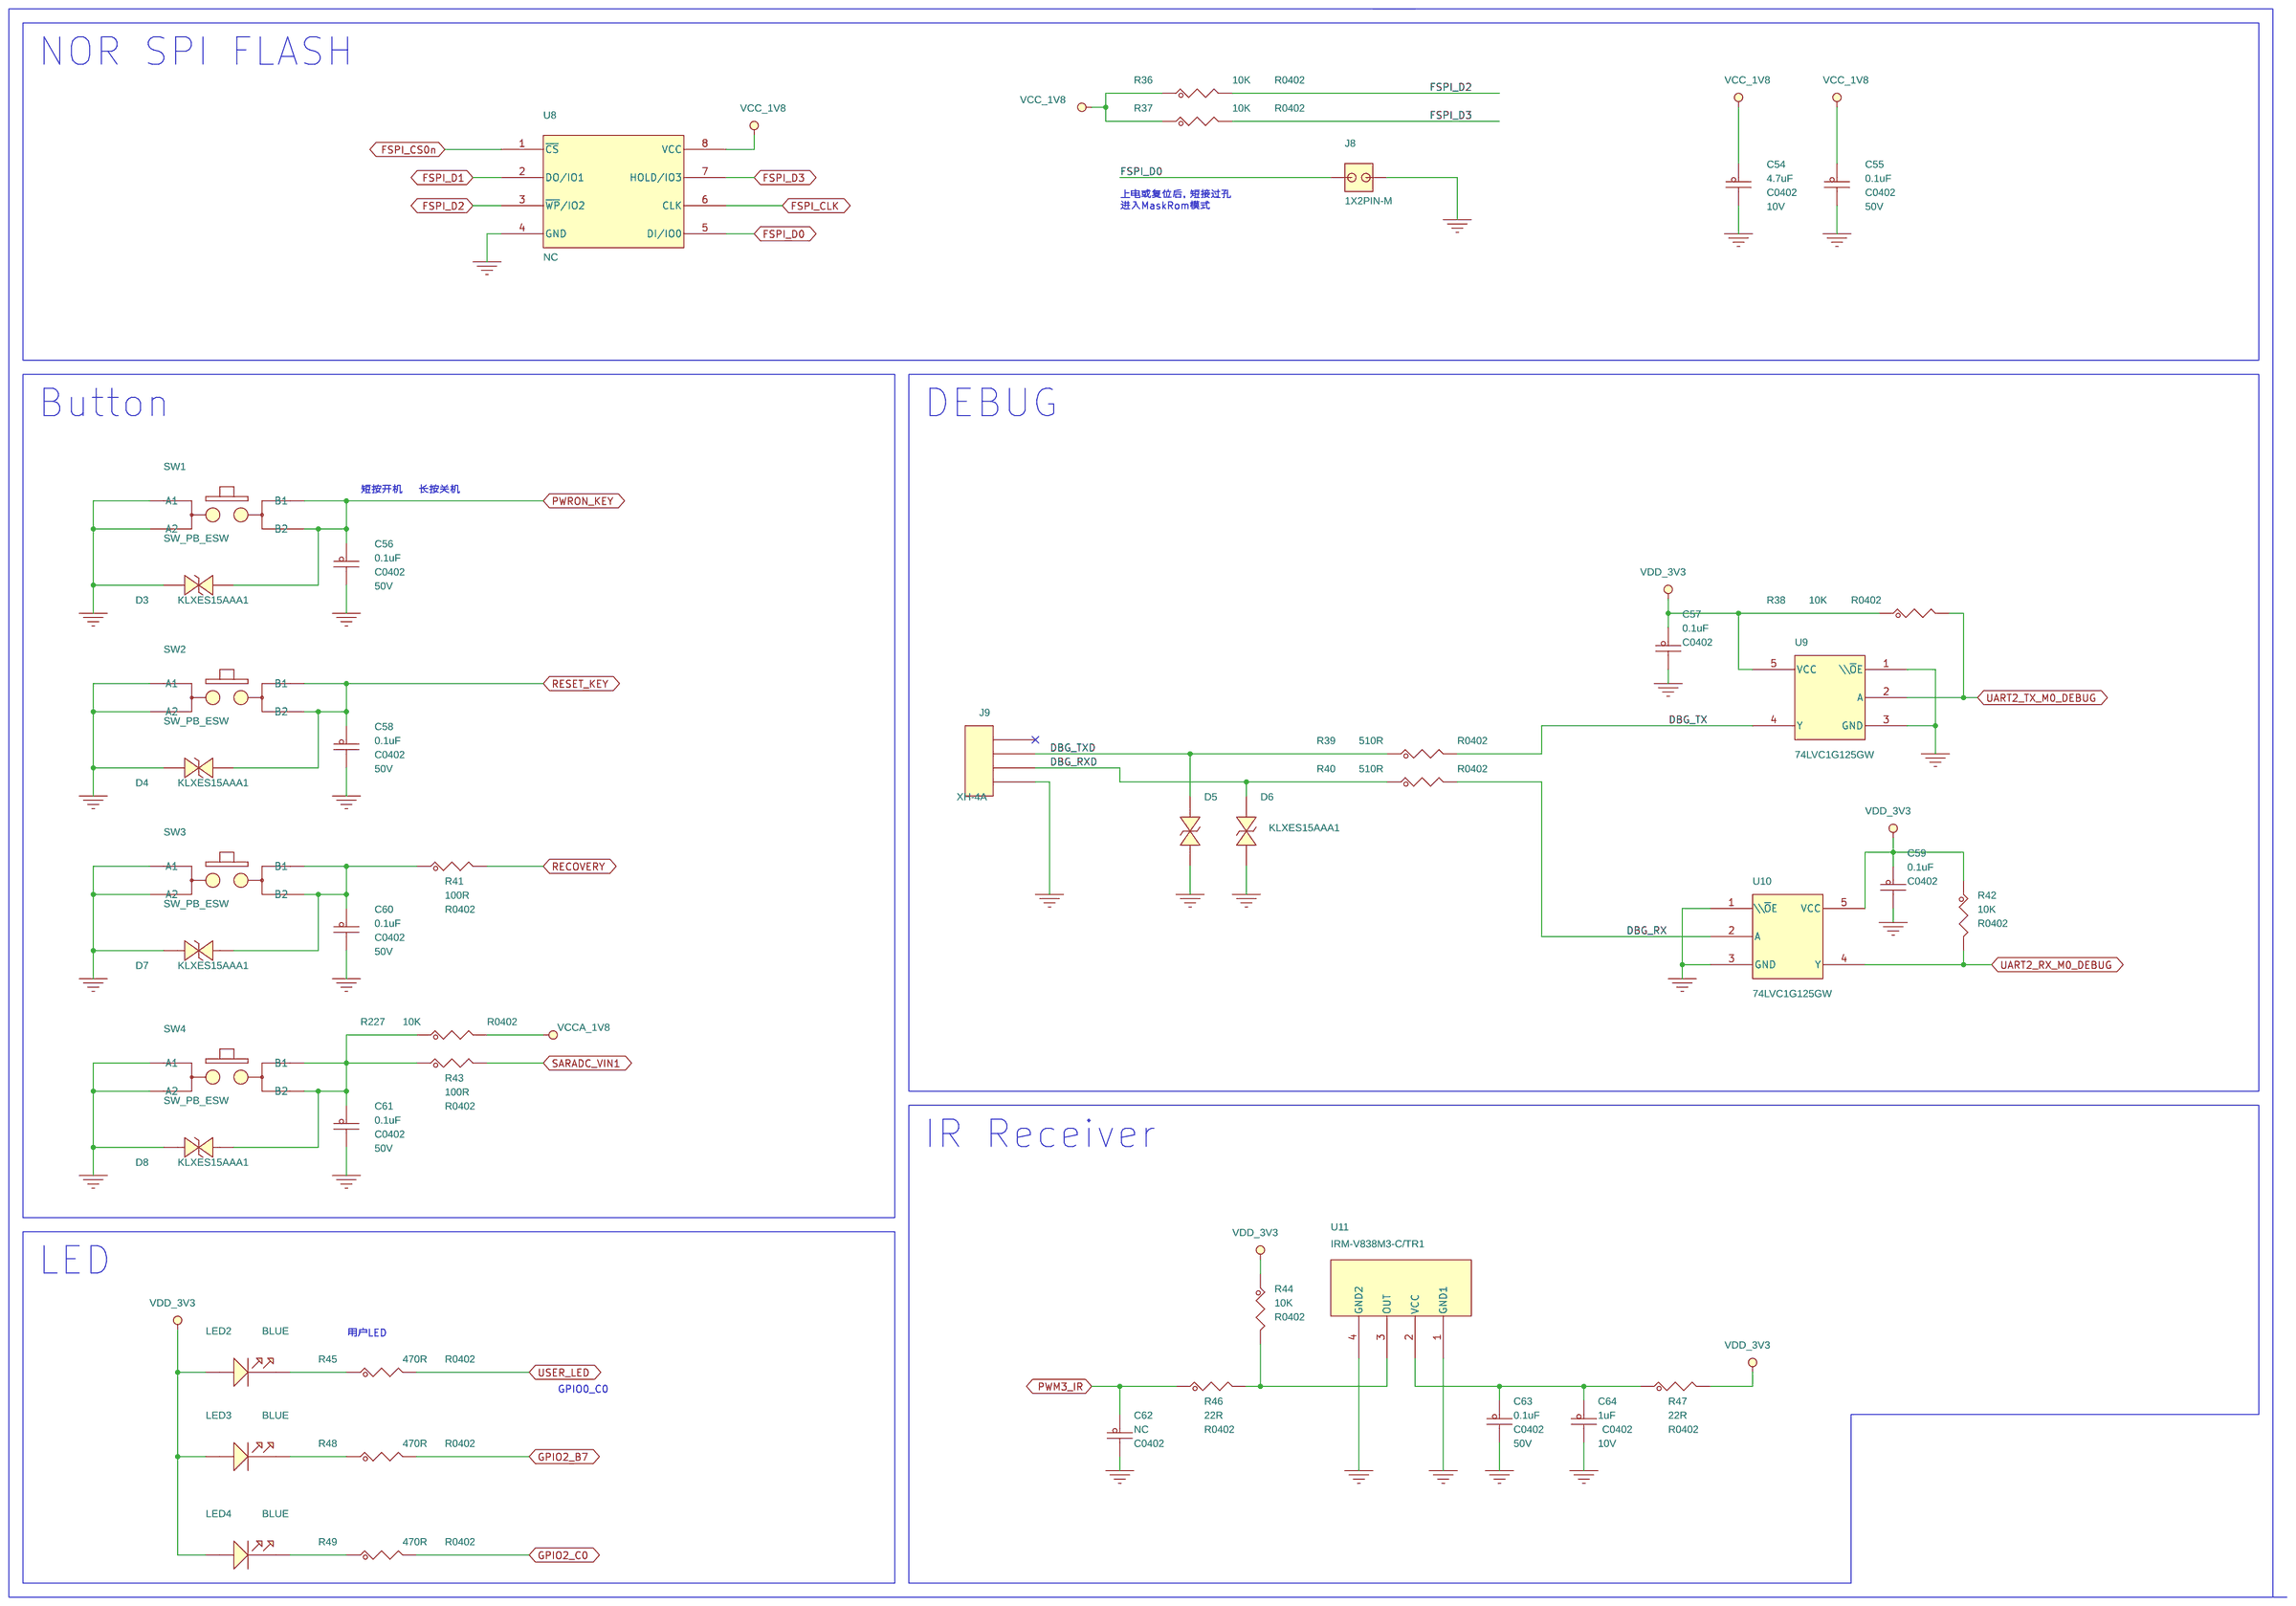
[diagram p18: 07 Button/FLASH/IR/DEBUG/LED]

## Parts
sheet 04 DC IN/POWER/FAN
C1  220uF  [EC6P3]
C2  10uF  [C0603]
C3  0.1uF  [C0402]
C4  0.1uF  [C0402]
C5  10uF  [C0603]
C6  0.1uF  [C0402]
C7  0.1uF  [C0402]
C8  NC  [C0402]
C9  0.1uF  [C0402]
C10  10uF  [C0603]
C11  0.1uF  [C0402]
C12  10uF  [C0603]
C13  10uF  [C0603]
C14  0.1uF  [C0402]
C15  22uF  [C0603]
C16  22uF  [C0603]
C17  0.1uF  [C0402]
C18  NC  [C0402]
C19  0.1uF  [C0402]
C20  NC  [C0402]
C21  10uF  [C0603]
C22  10uF  [C0603]
C23  0.1uF  [C0402]
C24  22uF  [C0603]
C25  22uF  [C0603]
C26  0.1uF  [C0402]
C27  NC  [C0402]
C28  0.1uF  [C0402]
C29  NC  [C0402]
C30  0.1uF  [C0402]
C31  10uF  [C0603]
C32  10uF  [C0603]
C33  0.1uF  [C0402]
C34  22uF  [C0603]
C35  22uF  [C0603]
C36  0.1uF  [C0402]
C37  NC  [C0402]
D1  SMAJ13CA  [SMA214-CA]
D2  1N4148W  [SOD-123]
F1  SMD1812P200TF16  [F1812]
H1  NPTH_M3  [NPTH_M3]
H2  NPTH_M3  [NPTH_M3]
H3  NPTH_M3  [NPTH_M3]
H4  NPTH_M3  [NPTH_M3]
J1  DC-044A-20A  [dc_in_th_3p_10r1x11r6]
J2  A1501WV-2P  [zh1p5mm_th_2p]
L1  3.3uH  [l4520]
L2  3.3uH  [l4520]
L3  3.3uH  [l4520]
LED1  RED  [LED0603]
Q1  AO3407  [SOT23]
Q2  SS8050  [SOT23]
Q3  SS8050  [SOT23]
R1  1K  [R0402]
R2  3.4K  [R0402]
R3  1K  [R0402]
R4  100K  [R0402]
R5  6.8K  [R0402]
R6  30K  [R0402]
R7  140K  [R0402]
R8  20K  [R0402]
R9  NC  [R0603]
R10  0R  [R0603]
R11  115K  [R0402]
R12  20K  [R0402]
R13  20K  [R0402]
R14  140K  [R0402]
R15  20K  [R0402]
R16  4.7K  [R0402]
R17  1K  [R0402]
R18  10K  [R0402]
R19  1K  [R0402]
R20  115K  [R0402]
R21  10K  [R0402]
R22  20K  [R0402]
R23  NC  [R0402]
R24  1K  [R0402]
R25  NC  [R0402]
U1  MT9700  [SOT23-5]
U2  MT9700  [SOT23-5]
U3  TP6327GS6  [SOT23_6]
U4  TP6327GS6  [SOT23_6]
U5  TP6327GS6  [SOT23_6]
sheet 07 Button/FLASH/IR/DEBUG/LED
C54  4.7uF  [C0402]
C55  0.1uF  [C0402]
C56  0.1uF  [C0402]
C57  0.1uF  [C0402]
C58  0.1uF  [C0402]
C59  0.1uF  [C0402]
C60  0.1uF  [C0402]
C61  0.1uF  [C0402]
C62  NC  [C0402]
C63  0.1uF  [C0402]
C64  1uF  [C0402]
D3  KLXES15AAA1  [ES0402]
D4  KLXES15AAA1  [ES0402]
D5  KLXES15AAA1  [ES0402]
D6  KLXES15AAA1  [ES0402]
D7  KLXES15AAA1  [ES0402]
D8  KLXES15AAA1  [ES0402]
J8  1X2PIN-M  [DIP-1x2-2P54]
J9  XH-4A  [XH2p54-4p]
LED2  BLUE  [LED0603]
LED3  BLUE  [LED0603]
LED4  BLUE  [LED0603]
R36  10K  [R0402]
R37  10K  [R0402]
R38  10K  [R0402]
R39  510R  [R0402]
R40  510R  [R0402]
R41  100R  [R0402]
R42  10K  [R0402]
R43  100R  [R0402]
R44  10K  [R0402]
R45  470R  [R0402]
R46  22R  [R0402]
R47  22R  [R0402]
R48  470R  [R0402]
R49  470R  [R0402]
R227  10K  [R0402]
SW1  SW_PB_ESW  [sw_3_2x4_2]
SW2  SW_PB_ESW  [sw_3_2x4_2]
SW3  SW_PB_ESW  [sw_3_2x4_2]
SW4  SW_PB_ESW  [sw_3_2x4_2]
U8  NC  [SOIC8-208]
U9  74LVC1G125GW  [SOT-353]
U10  74LVC1G125GW  [SOT-353]
U11  IRM-V838M3-C/TR1  [SMD4-6R80X2R50]
sheet 08 SD/RTC/RS232
C65  0.1uF  [C0402]
C66  0.1uF  [C0402]
C67  4.7uF  [C0402]
C68  0.1uF  [C0402]
C69  0.1uF  [C0402]
C70  0.1uF  [C0402]
C71  4.7uF  [C0402]
C72  0.1uF  [C0402]
D9  BAT54C  [SOT23]
D10  KLXES15AAA1  [ES0402]
D11  SMBJ15CA  [SMB-CA]
D12  SMBJ15CA  [SMB-CA]
D13  SMBJ15CA  [SMB-CA]
D14  SMBJ15CA  [SMB-CA]
D15  KLXES15AAA1  [ES0402]
D16  KLXES15AAA1  [ES0402]
D17  KLXES15AAA1  [ES0402]
D18  KLXES15AAA1  [ES0402]
D19  KLXES15AAA1  [ES0402]
D20  KLXES15AAA1  [ES0402]
D21  KLXES15AAA1  [ES0402]
J10  1.25T-2A  [gh1p25_th_2p]
J11  CON6  [DB2ERC-3P81-6P]
J12  TF_Card  [TFCARD]
R50  0R  [R0402]
R51  NC  [R0402]
R52  10K  [R0402]
R53  10K  [R0402]
R54  10K  [R0402]
R55  10K  [R0402]
R56  0R  [R0603]
R57  0R  [R0603]
R58  0R  [R0603]
R59  0R  [R0603]
R60  22R  [R0402]
R61  22R  [R0402]
R62  22R  [R0402]
R63  22R  [R0402]
R64  22R  [R0402]
R65  22R  [R0402]
R66  0R  [R0402]
U12  RX8010SJ  [SOP-8]
U13  MAX3232CSE  [SOIC16]
sheet 10 I2C/UART PORT
C75  10uF  [C0603]
D47  KLXES15AAA1  [ES0402]
D48  KLXES15AAA1  [ES0402]
D49  KLXES15AAA1  [ES0402]
D50  KLXES15AAA1  [ES0402]
D51  KLXES15AAA1  [ES0402]
D52  KLXES15AAA1  [ES0402]
D53  KLXES15AAA1  [ES0402]
D54  KLXES15AAA1  [ES0402]
J32  PH-4A  [PH-1X4-2P0]
J33  PH-4A  [PH-1X4-2P0]
J34  PH-4A  [PH-1X4-2P0]
J35  PH-4A  [PH-1X4-2P0]
R219  510R  [R0402]
R220  510R  [R0402]
R221  510R  [R0402]
R222  510R  [R0402]
R223  510R  [R0402]
R224  510R  [R0402]
R225  510R  [R0402]
R226  510R  [R0402]
sheet 16 MIPI CSI PORT
C140  0.1uF  [C0402]
C141  10uF  [C0603]
C142  0.1uF  [C0402]
C143  0.1uF  [C0402]
C144  10uF  [C0603]
C145  0.1uF  [C0402]
J23  FPC_0P5_24P_D  [fpc_24p_0p5]
J24  FPC_0P5_24P_D  [fpc_24p_0p5]
R176  0R  [R0402]
R177  NC  [R0402]
R178  0R  [R0402]
R179  1K  [R0402]
R180  NC  [R0402]
R181  6.8K  [R0402]
R182  0R  [R0402]
R183  NC  [R0402]
R184  0R  [R0402]
R185  NC  [R0402]
R186  1K  [R0402]
R187  6.8K  [R0402]
U32  MT9700  [SOT23-5]
U33  MT9700  [SOT23-5]
sheet 17 eDP_1.3/TP_PORT
C146  0.1uF  [C0402]
C147  0.1uF  [C0402]
C148  0.1uF  [C0402]
C149  10uF  [C0603]
C150  0.1uF  [C0402]
C151  0.1uF  [C0402]
C152  10uF  [C0603]
C153  0.1uF  [C0402]
J25  FPC_0R5_30P_D  [FPC-30P-0P5]
J26  PH-6A  [PH-1X6-2P0]
Q12  AO3407  [SOT23]
Q13  SS8050  [SOT23]
R188  NC  [R0402]
R189  10K  [R0402]
R190  10K  [R0402]
R191  NC  [R0402]
R192  1K  [R0402]
R193  0R  [R0603]
R194  6.8K  [R0402]
R195  20K  [R0402]
R196  1K  [R0402]
R197  10K  [R0402]
U34  MT9700  [SOT23-5]
sheet 18 MINI PCIE_PORT
C154  0.1uF  [C0402]
C155  NC  [C0402]
C156  10uF  [C0603]
C157  10uF  [C0603]
C158  0.1uF  [C0402]
C159  22uF  [C0603]
C160  22uF  [C0603]
C161  0.1uF  [C0402]
C162  33pF  [C0402]
C163  33pF  [C0402]
C164  33pF  [C0402]
C165  0.1uF  [C0402]
C166  0.1uF  [C0402]
C167  0.1uF  [C0402]
C168  0.1uF  [C0402]
C169  4.7uF  [C0402]
C170  4.7uF  [C0402]
D38  KLXES15AAA1  [ES0402]
D39  KLXES15AAA1  [ES0402]
J27  MINI-PCIE  [pcie_52p]
L10  3.3uH  [l4520]
R198  15K  [R0402]
R199  0R  [R0402]
R200  0R  [R0402]
R201  100K  [R0402]
R202  0R  [R0402]
R203  30K  [R0402]
R204  0R  [R0402]
R205  4.7K  [R0402]
R206  22R  [R0402]
R207  22R  [R0402]
R208  100R  [R0402]
R209  100R  [R0402]
R210  2.2R  [R0402]
R211  2.2R  [R0402]
SS5  M2X3mm  [t3r2-5r2_topsmt]
SS6  M2X3mm  [t3r2-5r2_topsmt]
U35  TP6327GS6  [SOT23_6]
U36  SIM-7-1  [nano_sim]
U37  NUP5120X6T1G  [SOT563]
sheet 19 AUDIO PORT
C171  1uF  [C0402]
C172  0.1uF  [C0402]
C173  1uF  [C0402]
C174  100pF  [C0603]
C175  220uF  [EC6P3]
C176  220uF  [EC6P3]
C177  0.1uF  [C0402]
D41  KLXES15AAA1  [ES0402]
D42  KLXES15AAA1  [ES0402]
D43  KLXES15AAA1  [ES0402]
D44  KLXES15AAA1  [ES0402]
D45  KLXES15AAA1  [ES0402]
D46  KLXES15AAA1  [ES0402]
J28  PJ-325C5-G  [EAR_JACK]
J29  PJ-325C5-R  [EAR_JACK]
J30  1X2PIN-M  [DIP-1x2-2P54]
J31  PH  [PH-1x2-2P0_l]
R212  120R  [R0402]
R213  2.2K  [R0402]
R214  10K  [R0402]
R215  22R  [R0402]
R216  0R  [R0402]
R217  2.2K  [R0402]
R218  0R  [R0402]

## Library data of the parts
C1 C175 C176 = CAP: Voltage: 16V; 规格: 贴片电解电容220uF 20% 16V 尺寸6.3mmX5.8mm 工作寿命：2000H@105℃; 规格编号: VZT221M1CTR-0606ACS; 规格书: 台湾立隆-贴片型铝电解电容.pdf; 价格: 0.566564; 类别: 贴片型铝电解电容; 品牌: 台湾立隆; 生命周期: 量产; 条码: EBF29060148
C2 C5 C10 C12 C13 C21 C22 C31 C32 C75 C141 C144 C149 C152 C156 C157 = CAP_NP: Voltage: 25V; 规格: 贴片电容10uF 20% 25V X5R 0603; 规格编号: CL10A106MA8NRNC; 规格书: 三星电容.pdf; 价格: 0.109811; 类别: 贴片电容0603; 品牌: 三星; 生命周期: 量产; 条码: EBF29060171
C3 C4 C6 C7 C9 C11 C14 C17 C19 C23 C26 C28 C30 C33 C36 C55 C56 C58 C60 C61 C63 C65 C66 C68-C70 C72 C140 C142 C143 C145-C148 C150 C151 C153 C154 C158 C161 C165-C168 = CAP_NP: Voltage: 50V; 规格: 贴片电容0.1uF 10% 50V X5R 0402; 规格编号: 0402X104K500NT; 规格书: 风华电容.pdf; 价格: 0.029826; 类别: 贴片电容0402; 品牌: 风华; 生命周期: 量产; 条码: EBF29060118
C8 C18 C20 C27 C29 C37 C62 C155 = CAP_NP: 规格: 贴片电容NC 预留; 类别: 贴片电容0402; 条码: EBF29060149
C15 C16 C24 C25 C34 C35 C159 C160 = CAP_NP: Voltage: 10V; 规格: 贴片电容22uF 20% 10V X5R 0603; 规格编号: CL10A226MP8NUNE; 规格书: 三星电容.pdf; 价格: 0.078818; 类别: 贴片电容0603; 品牌: 三星; 生命周期: 量产; 条码: EBF29060163
D1 = DIODE_BI-DIR_TRIG: 规格: TVS二极管 箝位电压21.5V 击穿电压14.4V 反向关断电压13V; 规格书: 伯恩半导体-SMAJ13CA.pdf; 价格: 0.181964; 类别: 贴片TVS; 品牌: 伯恩半导体; 生命周期: 量产; 条码: EBF29140049
D2 = DIODE: 规格: 开关二极管 反向耐压值100V 平均整流电流150mA 正向压降1.25V 150mA 功率500mW; 规格书: 1N4148WT4.pdf; 价格: 0.061637; 类别: 贴片开关二极管; 品牌: 江苏长电; 生命周期: 量产; 丝印: T4; 条码: EBF29140015
F1 = FUSE: 规格: 自恢复保险丝 最大电压46V 最大电流100A 保持电流2A 跳闸电流4A; 规格书: 瑞隆源-自恢复保险丝.pdf; 价格: 0.385618; 类别: 自恢复保险丝; 品牌: 瑞隆源; 生命周期: 量产; 条码: EBF29270006
H1-H4 = SPACER: 规格编号: M3螺丝孔_无铜; 类别: M3螺丝孔; 品牌: 野火科技有限公司; 生命周期: 量产; 条码: EBFCIS220926102704
J1 = DC-044A-20A: 规格: DC-044A-20A DC插座; 规格编号: DC-044A-20A DC; 规格书: DC插座_内径_2MM外径_5.9MM.pdf; 类别: DC电源座; 生命周期: 量产; 条码: EBF29040093
J2 = A1501WV-2P: 规格: ZH1.5直插 镀锡 2P 针座连接器; 规格书: A1501.pdf; 类别: 线对板连接器; 品牌: 长江连接器; 生命周期: 量产; 条码: EBF29040095
L1-L3 L10 = IND: 规格: 贴片电感3.3uH ±20% 3A 直流电阻69mΩ; 规格编号: TMPC0402HP-3R3MG-Z02; 规格书: 台庆-功率电感.pdf; 价格: 1.5992; 类别: 贴片电感0402; 品牌: 台庆; 生命周期: 量产; 条码: EBF29050040
LED1 = LED: 规格: 贴片LED RED 正向电流30mA 反向电压9V 功率消耗350mW 0603; 规格编号: 35B00617LGY-RED; 规格书: LED0603-RED.pdf; 类别: 贴片LED; 品牌: 亿光; 生命周期: 量产; 条码: EBF29140007
Q1 Q12 = MOSFET_P: 规格: P沟道MOS 导通电阻60mΩ 电流4.1A 3V可驱动; 规格书: 合科泰-AO3407.pdf; 价格: 0.199827; 类别: P-MOS; 品牌: 合科泰; 生命周期: 量产; 丝印: A7; 条码: EBF29280012
Q2 Q3 Q13 = NPN: 规格: 贴片三极管SS8050 集电极电流1.5A 额定功率300mW NPN; 规格书: 江苏长电-SS8050Y1.pdf; 价格: 0.086744; 类别: 贴片三极管SOT-23; 品牌: 江苏长电; 生命周期: 量产; 丝印: Y1; 条码: EBF29090001
R1 R3 R17 R19 R24 R179 R186 R192 R196 = RES: 规格: 贴片电阻1K 1% 1/16W 0402; 规格编号: RI0402L1001FT; 规格书: 合科泰-RI系列电阻.pdf; 类别: 贴片电阻0402; 品牌: 合科泰; 生命周期: 量产; 条码: EBF29070050
R2 = RES: 规格: 贴片电阻3.4K 1% 1/16W 0402; 规格编号: RI0402L3401FT; 规格书: 合科泰-RI系列电阻.pdf; 类别: 贴片电阻0402; 品牌: 合科泰; 生命周期: 量产; 条码: EBF29070186
R4 R201 = RES: 规格: 贴片电阻100K 1% 1/16W 0402; 规格编号: RI0402L1003FT; 规格书: 合科泰-RI系列电阻.pdf; 类别: 贴片电阻0402; 品牌: 合科泰; 生命周期: 量产; 条码: EBF29070054
R5 R181 R187 R194 = RES: 规格: 贴片电阻6.8K 1% 1/16W 0402; 规格编号: RI0402L6801FT; 规格书: 合科泰-RI系列电阻.pdf; 类别: 贴片电阻0402; 品牌: 合科泰; 生命周期: 量产; 条码: EBF29070052
R6 R203 = RES: 规格: 贴片电阻30K 1% 1/16W 0402; 规格编号: RI0402L3002FT; 规格书: 合科泰-RI系列电阻.pdf; 类别: 贴片电阻0402; 品牌: 合科泰; 生命周期: 量产; 条码: EBF29070048
R7 R14 = RES: 规格: 贴片电阻140K 1% 1/16W 0402; 规格编号: RI0402L1403FT; 规格书: 合科泰-RI系列电阻.pdf; 类别: 贴片电阻0402; 品牌: 合科泰; 生命周期: 量产; 条码: EBF29070058
R8 R12 R13 R15 R22 R195 = RES: 规格: 贴片电阻20K 1% 1/16W 0402; 规格编号: 0402WGF2002TCE; 规格书: 厚声-无铅厚膜电阻.pdf; 价格: 0.002473; 类别: 贴片电阻0402; 品牌: 厚声; 生命周期: 量产; 条码: EBF29070223
R9 = RES: 规格: 贴片电阻NC 预留; 类别: 贴片电阻0603; 条码: EBF29070088
R10 R56-R59 R193 = RES: 规格: 贴片电阻0R 1% 1/10W 0603; 规格编号: RI0603L0000FT; 规格书: 合科泰-RI系列电阻.pdf; 类别: 贴片电阻0603; 品牌: 合科泰; 生命周期: 量产; 条码: EBF29070063
R11 R20 = RES: 规格: 贴片电阻115K 1% 1/16W 0402; 规格编号: AC0402FR-07115KL; 规格书: YAGEO国巨厚膜无铅电阻.pdf; 价格: 0.006087; 类别: 贴片电阻0402; 品牌: 国巨; 生命周期: 量产; 条码: EBF29070290
R16 R205 = RES: 规格: 贴片电阻4.7K 1% 1/16W 0402; 规格编号: RI0402L4701FT; 规格书: 合科泰-RI系列电阻.pdf; 类别: 贴片电阻0402; 品牌: 合科泰; 生命周期: 量产; 条码: EBF29070047
R18 R21 R36-R38 R42 R44 R52-R55 R189 R190 R197 R214 R227 = RES: 规格: 贴片电阻10K 1% 1/16W 0402; 规格编号: 0402WGF1002TCE; 规格书: 厚声-无铅厚膜电阻.pdf; 价格: 0.002773; 类别: 贴片电阻0402; 品牌: 厚声; 生命周期: 量产; 条码: EBF29070046
R23 R25 R51 R177 R180 R183 R185 R188 R191 = RES: 规格: 贴片电阻NC 预留; 类别: 贴片电阻0402; 条码: EBF29070087
U1 U2 U32-U34 = MT9700: 规格: 负载开关 工作电压2.4V-5.5V 最大电流2A 过流保护; 规格书: MT9700.pdf; 价格: 0.483492; 类别: 功率开关; 品牌: 西安航天民芯; 生命周期: 量产; 丝印: D00HA-X; 条码: EBF29280004
U3-U5 U35 = TP6327GS6: 规格: DC-DC电源芯片 可输出电流 3A 开关工作频率 600kHz 输出类型 Adjustable 输出电压的路数 1 最小输入电压 3.5V 最大输入电压 18V; 规格书: TP6327GS6.pdf; 价格: 0.962255; 类别: 电源管理-DCDC; 品牌: 台舟; 生命周期: 量产; 条码: EBF29110045
C54 C67 C71 C169 C170 = CAP_NP: Voltage: 10V; 规格: 贴片电容4.7uF 10% 10V X5R 0402; 规格编号: CC0402KRX5R6BB475; 规格书: 国巨-贴片电容.pdf; 价格: 0.059058; 类别: 贴片电容0402; 品牌: 国巨; 生命周期: 量产; 条码: EBF29060248
C57 C59 C172 C177 = CAP_NP: voltage: 50V; 规格: 贴片电容0.1uF 10% 50V X5R 0402; 规格编号: 0402X104K500NT; 规格书: 风华电容.pdf; 价格: 0.029826; 类别: 贴片电容0402; 品牌: 风华; 生命周期: 量产; 条码: EBF29060118
C64 C171 C173 = CAP_NP: Voltage: 10V; 规格: 贴片电容1uF 10% 10V X5R 0402; 规格编号: 0402X105K100NT; 规格书: 风华电容.pdf; 价格: 0.01191; 类别: 贴片电容0402; 品牌: 风华; 生命周期: 量产; 条码: EBF29060121
D3-D8 D10 D15-D21 D38 D39 D41-D54 = DIODE_BI-DIR_TRIG: 规格: 用于 USB3.0、HDMI 0.5pF、5V、±15kV ESD 保护二极管; 规格书: KLXES15AAA1.pdf; 价格: 0.09719; 类别: 贴片ESD; 品牌: 永裕泰; 生命周期: 量产; 条码: EBF29140063
J8 = B2S: 规格: 蓝色排针 总PIN数2 间距2.54mm 直插; 规格书: 州日_单排针_直插_2P54.pdf; 类别: 直插单排排针; 生命周期: 量产; 条码: EBF29020019
J9 = CON4: 规格: 直针XH2.54-4P 间距2.54MM 拔插式 接插件 直插; 规格书: 博穆精密-XH2.54.pdf; 价格: 0.041116; 可替代料: EBF29040012; 类别: XH连接器; 品牌: 博穆精密; 生命周期: 量产; 条码: EBF29040012
LED2-LED4 = LED: 规格: 贴片LED BLUE 正向电流30mA 反向电压9V 功率消耗350mW 0603; 规格编号: 35B00617LGY-BLUE; 规格书: LED0603-BLUE.pdf; 类别: 贴片LED; 品牌: 亿光; 生命周期: 量产; 条码: EBF29140008
R39 R40 R219-R226 = RES: 规格: 贴片电阻510R 1% 1/16W 0402; 规格编号: 0402WGF5100TCE; 规格书: 厚声-无铅厚膜电阻.pdf; 价格: 0.003791; 类别: 贴片电阻0402; 品牌: 厚声; 生命周期: 量产; 条码: EBF29070293
R41 R43 R208 R209 = RES: 规格: 贴片电阻100R 1% 1/16W 0402; 规格编号: RI0402L1000FT; 规格书: 合科泰-RI系列电阻.pdf; 类别: 贴片电阻0402; 品牌: 合科泰; 生命周期: 量产; 条码: EBF29070053
R45 R48 R49 = RES: 规格: 贴片电阻470R 1% 1/16W 0402; 规格编号: 0402WGF4700TCE; 规格书: 厚声-无铅厚膜电阻.pdf; 价格: 0.002728; 类别: 贴片电阻0402; 品牌: 厚声; 生命周期: 量产; 条码: EBF29070284
R46 R47 R60-R65 R206 R207 R215 = RES: 规格: 贴片电阻22R 1% 1/16W 0402; 规格编号: RI0402L22R0FT; 规格书: 合科泰-RI系列电阻.pdf; 类别: 贴片电阻0402; 品牌: 合科泰; 生命周期: 量产; 条码: EBF29070181
SW1-SW4 = SW_PB_ESW: 规格: 3×4×2.5 160gf 轻触开关 白色; 规格编号: TS-1089S-AR02516; 规格书: 讯普3×4×2.5160GF轻触开.pdf; 价格: 0.168282; 类别: 贴片轻触开关; 品牌: 讯普; 生命周期: 量产; 条码: EBF29310006
U8 = W25QXX_8P: 规格: nor Flash 大小32Mb (4M x 8) 接口SPI-4I/O 工作电压1.7V~1.95V; 规格编号: W25Q32JWSSIQ; 规格书: 华邦W25Q32JWSSIQ.pdf; 价格: 2.95; 类别: 存储器-Flash; 品牌: 华邦; 生命周期: 量产; 条码: EBF2950030
U9 U10 = 74LVC1G125: 规格: 时钟缓冲器 驱动器 具有三态输出 允许工作电压为3.3V 5.5V 典型工作电流100mA; 规格书: 74LVC1G125GW.pdf; 价格: 0.182409; 类别: 隔离器件; 品牌: 安世; 生命周期: 量产; 丝印: VM; 条码: EBF29170001
U11 = IRM-V838M3-C_TR1: 规格: 侧贴红外遥控接收头 工作电压2.7V~5.5V 兼容TTL与CMOS; 规格书: IRM-V838M3-C_TR1.pdf; 类别: 红外接收头; 品牌: 亿光; 生命周期: 量产; 条码: EBF29230005
D9 = BAT54C: 规格: 肖特基二极管 直流反向耐压30V 平均整流电流200mA 正向压降1V@100mA SOT-23; 规格书: BAT54C.pdf; 价格: 0.068489; 类别: 贴片肖特基二极管; 品牌: 萨科微; 生命周期: 量产; 丝印: KL3; 条码: EBF29140014
D11-D14 = DIODE_BI-DIR_TRIG: 规格: TVS二极管 箝位电压24.4V 击穿电压16.7V 反向关断电压15V; 规格书: 君耀电子-SMBJ15CA.pdf; 价格: 0.197164; 类别: 贴片TVS; 品牌: 君耀电子; 生命周期: 量产; 条码: EBF29140024
J10 = 1.25T-2A: 规格: GH1.25直插 2P针座连接器; 规格书: 1.25T-2A.pdf; 类别: 线对板连接器; 品牌: 创都; 生命周期: 量产; 条码: EBF29040105
J11 = CON6: 规格: 绿色插拔式接线端子 间距3.81mm 90度弯针 6PIN; 规格编号: WJ15EDGRC-3.81-6P; 规格书: 康奈克斯电气-绿色端子弯针插座.pdf; 价格: 0.301748; 类别: 绿色插拔式接线端子; 品牌: 康奈克斯电气; 生命周期: 量产; 条码: EBF29040013
J12 = TF_Card: 规格: MICRO SD 卡座 TF T-Flash 外焊 双压片 自弹贴片; 规格编号: TF-015; 规格书: 硕方-TF-015.pdf; 价格: 0.48; 可替代料: EBF29040003; 类别: SD卡连接器; 品牌: 硕方; 生命周期: 量产; 条码: EBF29040003
R50 R66 R176 R178 R182 R184 R199 R200 R202 R204 R216 R218 = RES: 规格: 贴片电阻0R 1% 1/16W 0402; 规格编号: RI0402L000FT; 规格书: 合科泰-RI系列电阻.pdf; 类别: 贴片电阻0402; 品牌: 合科泰; 生命周期: 量产; 条码: EBF29070049
U12 = RX8010SJ: 规格: 工作电压1.6V~5.5V 日期格式YY-MM-DD 时间格式HH:MM:SS 接口类型I2C 存储器容量16B 电流消耗350nA @ 5V; 规格书: 爱普生-RX8010SJ.pdf; 价格: 34.17; 类别: 实时时钟芯片; 品牌: 爱普生; 生命周期: 量产; 条码: EBF29180001
U13 = MAX3232CSE: 规格: RS232芯片 收发器 驱动器/接收器数：2/2 协议类别RS232 电源电压3V~5.5V 数据速率235kbps; 规格编号: MAX3232CSE+T; 规格书: MAX3232CSE.pdf; 价格: 7.73; 类别: RS232芯片; 品牌: 美信; 生命周期: 量产; 丝印: MAX3232; 条码: EBF29150006
J32-J35 = 1X4PIN: 规格: 直针PH2.0-4P 间距2.0MM 拔插式 接插件; 规格书: 博穆精密-PH2.0.pdf; 价格: 0.017; 可替代料: EBF29020025; 类别: PH连接器; 品牌: 博穆精密; 生命周期: 量产; 条码: EBF29020025
J23 J24 = FPC-24P: 规格: FPC连接器 针脚数24 间距0.5mmm 下接 卧贴 翻盖式; 规格编号: AFC01-S24FCA-00; 规格书: 钜硕电子-FPC间距0.5mm.pdf; 价格: 0.368739; 可替代料: EBF29040059; 类别: FPC连接器; 品牌: 钜硕电子; 生命周期: 量产; 条码: EBF29040059
J25 = FPC-30P: 规格: FPC连接器 针脚数30 间距0.5mm 高度2.0mm 下接 卧贴 翻盖式; 规格编号: FPC-05F-30PH20; 规格书: FPC-05F-NPH20.pdf; 类别: FPC连接器; 品牌: 讯普; 生命周期: 量产; 条码: EBF29040079
J26 = 1X6PIN: 规格: 直针PH2.0-6P 间距2.0MM 拔插式 接插件; 规格书: 博穆精密_PH2.0-A.pdf; 价格: 0.0228; 可替代料: EBF29020026; 类别: PH连接器; 品牌: 博穆精密; 生命周期: 量产; 条码: EBF29020026
C162-C164 = CAP_NP: Voltage: 50V; 规格: 贴片电容33pF 5% 50V 0402; 规格编号: 0402CG330J500NT; 规格书: 风华电容.pdf; 类别: 贴片电容0402; 品牌: 风华; 生命周期: 量产; 条码: EBF29060298
J27 = MINI-PCIE: 规格: MINI PCIE插座 引脚数：52P; 规格编号: PCIE-52P56H; 规格书: XUNPU(讯普)_52PMINIPCIE插座.pdf; 价格: 1.935; 可替代料: EBF29040055; 类别: 金手指连接器; 品牌: 讯普; 生命周期: 量产; 条码: EBF29040055
R198 = RES: 规格: 贴片电阻15K 1% 1/16W 0402; 规格编号: RI0402L1502FT; 规格书: 合科泰-RI系列电阻.pdf; 类别: 贴片电阻0402; 品牌: 合科泰; 生命周期: 量产; 条码: EBF29070222
R210 R211 = RES: 规格: 贴片电阻2.2R 1% 1/16W 0402; 规格编号: 0402WGF220KTCE; 规格书: 厚声-无铅厚膜电阻.pdf; 价格: 0.003072; 类别: 贴片电阻0402; 品牌: 厚声; 生命周期: 量产; 条码: EBF29070280
SS5 SS6 = SPACER: 规格: SMT贴片螺母M2 高度3MM 台阶外径：4.5MM 整体高度：4.5MM 焊接孔外径：3MM; 规格编号: ZIY01-001; 规格书: 雄和远景_SMTWE2040CTJ.pdf; 类别: 贴片螺母; 品牌: 雄和远景; 生命周期: 量产; 条码: EBF500026
U36 = SIM-7-1: 规格: nano sim卡座; 规格编号: HYC63-SIM07-137; 规格书: 华宇创_NANOSIMPUSH1.37H带CDPIN带柱.pdf; 价格: 1.48; 可替代料: EBF29040054; 类别: SIM卡座连接器; 品牌: 华宇创; 生命周期: 量产; 条码: EBF29040054
U37 = NUP5120-D: 规格: 防静电保护ESD二极管 击穿电压6.2V 反向关断电压5V 封装SOT-523; 规格书: 安森美_NUP5120X6T1G.pdf; 价格: 0.39; 类别: 贴片ESD; 品牌: 安森美; 生命周期: 量产; 条码: EBF29140034
C174 = CAP_NP: Voltage: 50V; 规格: 贴片电容100pF 5% 50V C0G 0603; 规格编号: 0603CG101J500NT; 规格书: 风华电容.pdf; 价格: 0.014181; 类别: 贴片电容0603; 品牌: 风华; 生命周期: 量产; 条码: EBF29060132
J28 = MIC_JACK: 规格: 音频插座 耳机插座 双声道 3.5mm耳机座 5脚 绿; 规格书: 星坤-音频连接器.pdf; 价格: 0.24; 可替代料: EBF29020024; 类别: 耳机座; 品牌: 中国星坤; 生命周期: 量产; 条码: EBF29020024
J29 = MIC_JACK: 规格: 音频插座 耳机插座 双声道 3.5mm耳机座 5脚 粉; 规格书: 星坤-音频连接器.pdf; 价格: 0.24; 可替代料: EBF29020023; 类别: 耳机座; 品牌: 中国星坤; 生命周期: 量产; 条码: EBF29020023
J30 = B2S: 规格: 排针 总PIN数2 间距2.54mm 直插; 规格书: 州日_单排针_直插_2P54.pdf; 类别: 直插单排排针; 生命周期: 量产; 条码: EBF29020034
J31 = 1X2PIN: 规格: 直针PH2.0-2P 间距2.0MM 拔插式 接插件; 规格编号: PH-2A; 规格书: 博穆精密_PH2.0-A.pdf; 价格: 0.019031; 可替代料: EBF29040005; 类别: PH连接器; 品牌: 博穆精密; 生命周期: 量产; 条码: EBF29040005
R212 = RES: 规格: 贴片电阻120R 1% 1/16W 0402; 规格编号: 0402WGF1200TCE; 规格书: 厚声-无铅厚膜电阻.pdf; 价格: 0.002198; 类别: 贴片电阻0402; 品牌: 厚声; 生命周期: 量产; 条码: EBF29070275
R213 R217 = RES: 规格: 贴片电阻2.2K 1% 1/16W 0402; 规格编号: RI0402L2201FT; 规格书: 合科泰-RI系列电阻.pdf; 类别: 贴片电阻0402; 品牌: 合科泰; 生命周期: 量产; 条码: EBF29070051

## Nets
3V3_EDP: C149.1 C150.1 J25.12 J25.13 J26.1 R188.1 R189.1 R190.1 U34.1(OUT)
5V0_CAM_1: C141.1 C142.1 J23.1 J23.2 J23.3 U32.1(OUT)
5V0_CAM_2: C144.1 C145.1 J24.1 J24.2 J24.3 U33.1(OUT)
12V_EDP: C152.1 C153.1 J25.26 J25.27 J25.28 J25.29 Q12.3(DRAIN)
GND: C1.2 C2.2 C3.2 C4.2 C5.2 C6.2 C9.2 C10.2 C11.2 C12.2 C13.2 C14.2 C15.2 C16.2 C17.2 C18.1 C21.2 C22.2 C23.2 C24.2 C25.2 C26.2 C27.1 C30.2 C31.2 C32.2 C33.2 C34.2 C35.2 C36.2 C37.1 C54.2 C55.2 C56.2 C57.2 C58.2 C59.2 C60.2 C61.2 C62.2 C63.2 C64.2 C65.2 C66.2 C67.2 C68.2 C71.2 C72.2 C75.2 C140.2 C141.2 C142.2 C143.2 C144.2 C145.2 C148.2 C149.2 C150.2 C152.2 C153.2 C156.2 C157.2 C158.2 C159.2 C160.2 C161.2 C162.2 C163.2 C164.2 C167.2 C168.2 C169.2 C170.2 C171.2 C172.2 C173.2 C177.2 D1.2 D2.2(A) D3.1 D4.1 D5.1 D6.1 D7.1 D8.1 D10.1 D11.1 D12.1 D13.1 D14.1 D15.1 D16.1 D17.1 D18.1 D19.1 D20.1 D21.1 D38.1 D39.1 D41.1 D42.1 D43.1 D44.1 D45.1 D46.1 D47.1 D48.1 D49.1 D50.1 D51.1 D52.1 D53.1 D54.1 J1.1 J1.2 J1.3 J1.5 J2.2 J8.1 J9.4 J10.2 J11.2 J11.5 J12.6(VSS) J12.10(GND10) J12.11(GND11) J12.12(GND12) J12.13(GND13) J23.4 J23.18 J23.21 J23.23 J23.24 J23.25(SH1) J23.26(SH2) J24.4 J24.23 J24.24 J24.25(SH1) J24.26(SH2) J25.2 J25.5 J25.8 J25.11 J25.15 J25.16 J25.18 J25.19 J25.20 J25.21 J25.31(SH1) J25.32(SH2) J26.6 J27.4(GND9) J27.9(GND1) J27.15(GND2) J27.18(GND10) J27.21(GND3) J27.26(GND11) J27.27(GND4) J27.29(GND5) J27.34(GND12) J27.35(GND6) J27.37(GND7) J27.40(GND13) J27.43(GND8) J27.50(GND14) J27.53 J27.54 J32.4 J33.4 J34.4 J35.4 Q2.2(EMITTER) Q3.2(EMITTER) Q13.2(EMITTER) R2.2 R5.2 R6.2 R8.2 R13.2 R15.2 R18.2 R21.2 R22.2 R25.2 R181.2 R187.2 R191.1 R194.2 R197.2 R203.2 R216.2 R217.2 R218.2 SS5.1(NC) SS6.1(NC) SW1.1(A1) SW1.2(A2) SW2.1(A1) SW2.2(A2) SW3.1(A1) SW3.2(A2) SW4.1(A1) SW4.2(A2) U1.2(GND) U2.2(GND) U3.1(GND) U4.1(GND) U5.1(GND) U8.4(GND) U9.1(\\~{O}E) U9.3(GND) U10.1(\\~{O}E) U10.3(GND) U11.1(GND1) U11.4(GND2) U12.4(GND) U13.15(GND) U32.2(GND) U33.2(GND) U34.2(GND) U35.1(GND) U36.5(GND) U36.8(SH1) U36.9(SH2) U36.10(SH3) U36.11(SH4) U37.2 ; also on sheet 1 5 6 7 8 9 10 11
VCC3V3_SD: C71.1 C72.1 J12.4(VDD) ; also on sheet 6
VCC3V3_SYS: C8.1 C15.1 C16.1 C17.1 L1.2 R4.1 U1.5(IN) U34.5(IN) ; also on sheet 5 11
VCC5V0_SYS: C20.1 C24.1 C25.1 C26.1 L2.2 R11.1 R16.1 U2.5(IN) U32.5(IN) U33.5(IN) ; also on sheet 6 11
VCC5V0_SYS_2: C29.1 C34.1 C35.1 C36.1 L3.2 R10.1 R20.1 ; also on sheet 5 9
VCC_1V8: C54.1 C55.1 R36.1 R37.1 U8.8(VCC) ; also on sheet 6 8
VCC_12V: C1.1 C2.1 C3.1 C12.1 C13.1 C14.1 C21.1 C22.1 C23.1 C31.1 C32.1 C33.1 C151.1 C156.1 C157.1 C158.1 D1.1 F1.2 R7.1 R9.1 R14.1 R23.1 R193.1 R195.1 U3.3(VIN) U4.3(VIN) U5.3(VIN) U35.3(VIN) ; also on sheet 5
VCC_RTC: R51.2 ; also on sheet 6
VCCA_1V8: R227.2 ; also on sheet 6
VCCIO_ACODEC: C172.1 C177.1 R212.1 R214.1 ; also on sheet 6
VDD_3V3: C5.1 C6.1 C57.1 C59.1 C67.1 C75.1 D9.2 J32.1 J33.1 J34.1 J35.1 LED2.2(ANODE) LED3.2(ANODE) LED4.2(ANODE) R38.1 R42.1 R44.1 R47.2 R52.1 R53.1 R54.1 R55.1 U1.1(OUT) U9.5(VCC) U10.5(VCC) U13.16(VCC) ; also on sheet 1 7 8 9 10 11
VDD_5V: C10.1 C11.1 U2.1(OUT) ; also on sheet 10
CAM0_nRST: J23.22 ; also on sheet 6
CAM0_PWDN: J23.15 ; also on sheet 6
CAM0_PWR_EN: R179.1 ; also on sheet 6
CAM1_nRST: J24.22 ; also on sheet 6
CAM1_PWDN: J24.15 ; also on sheet 6
CAM1_PWR_EN: R186.1 ; also on sheet 6
CSI_RX_D2N_S0: J23.17 R178.2
CSI_RX_D2N_S1: J24.12 R180.2
CSI_RX_D2P_S0: J23.16 R176.2
CSI_RX_D2P_S1: J24.11 R177.2
CSI_RX_D3N_S0: J23.20 R184.2
CSI_RX_D3N_S1: J24.8 R185.2
CSI_RX_D3P_S0: J23.19 R182.2
CSI_RX_D3P_S1: J24.7 R183.2
DBG_RX: R40.2 U10.2(A)
DBG_RXD: D6.2 J9.3 R40.1
DBG_TX: R39.2 U9.4(Y)
DBG_TXD: D5.2 J9.2 R39.1
DM4: D38.2 J27.36(USB-D-) R210.1
DP4: D39.2 J27.38(USB-D+) R211.1
EDP_AUXN: C146.2 J25.10 R191.2
EDP_AUXP: C147.2 J25.9 R188.2
EDP_BL_EN: J25.22 ; also on sheet 6
EDP_BL_PWM: J25.23 ; also on sheet 6
EDP_HPDIN_M0: J25.17 ; also on sheet 6
EDP_PWR_EN: R192.1 R196.1 ; also on sheet 6
EDP_TP_INT: J26.2 R189.2 ; also on sheet 6
EDP_TP_RESET: J26.3 R190.2 ; also on sheet 6
EDP_TX_AUXN: C146.1 ; also on sheet 6
EDP_TX_AUXP: C147.1 ; also on sheet 6
EDP_TX_D0N: J25.6 ; also on sheet 6
EDP_TX_D0P: J25.7 ; also on sheet 6
EDP_TX_D1N: J25.3 ; also on sheet 6
EDP_TX_D1P: J25.4 ; also on sheet 6
EXT_PWR_EN: R1.1 R3.1 R19.1 R24.1 ; also on sheet 6
FAN: C30.1 Q1.2(SOURCE) R9.2 R10.2 R12.1
FSPI_CLK: U8.6(CLK) ; also on sheet 6
FSPI_CS0n: U8.1(~{CS}) ; also on sheet 6
FSPI_D0: J8.2 U8.5(DI/IO0) ; also on sheet 6
FSPI_D1: U8.2(DO/IO1) ; also on sheet 6
FSPI_D2: R36.2 U8.3(~{WP}/IO2) ; also on sheet 6
FSPI_D3: R37.2 U8.7(HOLD/IO3) ; also on sheet 6
GPIO2_B7: R48.2 ; also on sheet 6
GPIO2_C0: R49.2 ; also on sheet 6
HP_DET: C173.1 R215.1 ; also on sheet 6
HP_SNS: J28.1 J29.1 R216.1 R218.1 ; also on sheet 6
HPL_OUT: C175.1 ; also on sheet 6
HPR_OUT: C176.1 ; also on sheet 6
HUB_DM4: R210.2 ; also on sheet 9
HUB_DP4: R211.2 ; also on sheet 9
I2C0_SCL_PMIC: U12.6(SCL) ; also on sheet 6
I2C0_SDA_PMIC: U12.5(SDA) ; also on sheet 6
I2C1_SCL: J23.6 ; also on sheet 6 11
I2C1_SDA: J23.5 ; also on sheet 6 11
I2C2_SCL_M1: R222.2 ; also on sheet 6
I2C2_SDA_M1: R221.2 ; also on sheet 6
I2C3_SCL_M0: R219.2 ; also on sheet 6
I2C3_SDA_M0: R220.2 ; also on sheet 6
I2C4_SCL_M0: J26.4 ; also on sheet 6
I2C4_SDA_M0: J26.5 ; also on sheet 6
I2C5_SCL_M0: J24.6 ; also on sheet 6 11
I2C5_SDA_M0: J24.5 ; also on sheet 6 11
MIC_INN: C174.2 D44.2 J30.1 R217.1 ; also on sheet 6
MIC_INP: C174.1 D41.2 J29.2 J29.3 J29.4 J29.5 J30.2 R213.2 ; also on sheet 6
MINIPCIE_3V3: C155.1 C159.1 C160.1 C161.1 C167.1 C168.1 C169.1 C170.1 J27.2(VBAT1) J27.24(VBAT5) J27.39(VBAT2) J27.41(VBAT3) J27.52(VBAT4) L10.2 R201.1 R205.1
MINIPCIE_nWDISABLE: R208.2 ; also on sheet 6
MIPI_CSI_RX_CLK0N: J23.10 ; also on sheet 6
MIPI_CSI_RX_CLK0P: J23.9 ; also on sheet 6
MIPI_CSI_RX_CLK1N: J24.10 ; also on sheet 6
MIPI_CSI_RX_CLK1P: J24.9 ; also on sheet 6
MIPI_CSI_RX_D0N: J23.12 ; also on sheet 6
MIPI_CSI_RX_D0P: J23.11 ; also on sheet 6
MIPI_CSI_RX_D1N: J23.8 ; also on sheet 6
MIPI_CSI_RX_D1P: J23.7 ; also on sheet 6
MIPI_CSI_RX_D2N: R178.1 R180.1 ; also on sheet 6
MIPI_CSI_RX_D2P: R176.1 R177.1 ; also on sheet 6
MIPI_CSI_RX_D3N: R184.1 R185.1 ; also on sheet 6
MIPI_CSI_RX_D3P: R182.1 R183.1 ; also on sheet 6
PCIE20_CLKREQn_M0: R207.1 ; also on sheet 6
PCIE20_PERSTn_M0: R209.2 ; also on sheet 6
PCIE20_REFCLKN: J27.11(VDD-EXT) ; also on sheet 6
PCIE20_REFCLKP: J27.13(RESERVED) ; also on sheet 6
PCIE20_RXN: J27.23(UART-RXD) ; also on sheet 6
PCIE20_RXP: J27.25(UART-RTS) ; also on sheet 6
PCIE20_TXN: C165.1 ; also on sheet 6
PCIE20_TXP: C166.1 ; also on sheet 6
PCIE20_WAKEn_M0: R206.1 ; also on sheet 6
PCIE_PWR_EN: R204.1 ; also on sheet 6
PE_TXN: C165.2 J27.31(UART-TXD)
PE_TXP: C166.2 J27.33(PERST2)
PWM2_M0: R17.1 ; also on sheet 6
PWM3_IR: C62.1 R46.1 ; also on sheet 6
PWRON_KEY: C56.1 D3.2 SW1.3(B1) SW1.4(B2) ; also on sheet 6
RECOVERY: R41.2 ; also on sheet 6
RESET_KEY: C58.1 D4.2 SW2.3(B1) SW2.4(B2) ; also on sheet 6
RX8010_nIRQ1: U12.7(/IRQ1) ; also on sheet 6
RX8010_nIRQ2: U12.3(/IRQ2) ; also on sheet 6
RXD1_232: D12.2 R58.1 U13.13(R1IN)
RXD2_232: D11.2 R56.1 U13.8(R2IN)
SARADC_VIN1: R43.2 ; also on sheet 6
SDMMC0_CLK: R63.1 ; also on sheet 6
SDMMC0_CMD: R62.1 ; also on sheet 6
SDMMC0_D0: R64.1 ; also on sheet 6
SDMMC0_D1: R65.1 ; also on sheet 6
SDMMC0_D2: R60.1 ; also on sheet 6
SDMMC0_D3: R61.1 ; also on sheet 6
SDMMC0_DET: R66.1 ; also on sheet 6
SIM_CLK0: J27.12(USIM-CLK) R200.1
SIM_DATA0: J27.10(USIM-DATA) R202.1
SIM_RST0: J27.14(USIM-RST) R199.1
SIM_VDD: J27.8(USIM-VDD) R198.1 U36.1(VCC) U37.1
SPKN_OUT: D46.2 J31.2 ; also on sheet 6
SPKP_OUT: D45.2 J31.1 ; also on sheet 6
TXD1_232: D14.2 R59.1 U13.14(T1OUT)
TXD2_232: D13.2 R57.1 U13.7(T2OUT)
UART2_RX_M0_DEBUG: R42.2 U10.4(Y) ; also on sheet 6
UART2_TX_M0_DEBUG: R38.2 U9.2(A) ; also on sheet 6
UART3_RX_M1: R52.2 U13.9(R2OUT) ; also on sheet 6
UART3_TX_M1: R53.2 U13.10(T2IN) ; also on sheet 6
UART4_RX_M1: R54.2 U13.12(R1OUT) ; also on sheet 6
UART4_TX_M1: R55.2 U13.11(T1IN) ; also on sheet 6
UART7_RX_M0: R223.2 ; also on sheet 6
UART7_TX_M0: R224.2 ; also on sheet 6
UART9_RX_M1: R225.2 ; also on sheet 6
UART9_TX_M1: R226.2 ; also on sheet 6
USER_LED: R45.2 ; also on sheet 6
N02088: F1.1 J1.4
N03633: C7.1 U3.6(BOOT)
N03641: C7.2 L1.1 U3.2(SW)
N03801: C8.2 R4.2 R6.1 U3.4(FB)
N28501: C28.1 U5.6(BOOT)
N28533: C28.2 L3.1 U5.2(SW)
N15118698: C4.1 R1.2 U1.4(EN)
N15119063: R2.1 U1.3(ISET)
N15122947: C9.1 R3.2 U2.4(EN)
N15123057: R5.1 U2.3(ISET)
N15659726: C18.2 R7.2 R8.1 U3.5(EN)
N15830872: C176.2 D43.2 J28.3 J28.5
N15830941: C175.2 D42.2 J28.2 R215.2
N15838979: J28.4 R214.2
N15851038: C171.1 R212.2 R213.1
N16735828: LED2.1(CATHODE) R45.1
N16735933: LED3.1(CATHODE) R48.1
N16793147: D15.2 J12.1(DAT2) R60.2
N16793149: D19.2 J12.7(DAT0) R64.2
N16793151: D18.2 J12.5(CLK) R63.2
N16793153: D17.2 J12.3(CMD) R62.2
N16793155: D16.2 J12.2(CD/DAT3) R61.2
N16793157: D20.2 J12.8(DAT1) R65.2
N16793300: D21.2 J12.9(CD) R66.2
N16795570: LED4.1(CATHODE) R49.1
N16795883: C37.2 R23.2 R24.2 R25.1 U5.5(EN)
N16811933: J27.1(MIC-P) R205.2 R206.2
N16823854: J27.7(SPK-N) R207.2
N16928945: J27.20(W-DISABLE) R208.1
N16929135: J27.22(PERST1) R209.1
N16980859: C164.1 R199.2 U36.2(RST) U37.6
N16980861: C163.1 R200.2 U36.3(CLK) U37.4
N16980863: C162.1 R198.2 R202.2 U36.7(I/O) U37.5
N17405290: C29.2 R20.2 R22.1 U5.4(FB)
N17423559: C19.1 U4.6(BOOT)
N17423580: C19.2 L2.1 U4.2(SW)
N17423608: C27.2 R14.2 R15.1 U4.5(EN)
N17423737: C20.2 R11.2 R13.1 U4.4(FB)
N17454508: C69.2 U13.1(C1+)
N17454513: C69.1 U13.3(C1-)
N17455367: C70.2 U13.4(C2+)
N17455372: C70.1 U13.5(C2-)
N17455499: C68.1 U13.6(V-)
N17455508: C66.1 U13.2(V+)
N17592125: C154.1 U35.6(BOOT)
N17592129: C154.2 L10.1 U35.2(SW)
N17592172: C155.2 R201.2 R203.1 U35.4(FB)
N17592220: R204.2 U35.5(EN)
N17685591: C151.2 Q12.1(GATE) Q13.3(COLLECTOR) R195.2
N17685601: Q13.1(BASE) R196.2 R197.1
N17685851: Q12.2(SOURCE) R193.2
N17690217: R194.1 U34.3(ISET)
N17690290: C148.1 R192.2 U34.4(EN)
N17697880: R181.1 U32.3(ISET)
N17697953: C140.1 R179.2 U32.4(EN)
N17731599: J11.6 R59.2
N17731608: J11.4 R58.2
N17731627: J11.1 R56.2
N17750545: Q1.1(GATE) Q2.3(COLLECTOR) R12.2
N17750554: D2.1(K) J2.1 Q1.3(DRAIN)
N17750632: Q2.1(BASE) R17.2 R18.1
N17759502: C65.1 D9.3 U12.8(VDD)
N17861933: C63.1 C64.1 R47.1 U11.2(VCC)
N17863087: R44.2 R46.2 U11.3(OUT)
N17946485: C60.1 D7.2 R41.1 SW3.3(B1) SW3.4(B2)
N17975561: D10.2 J10.1 R50.2 R51.1
N18091011: D9.1 R50.1
N18115454: R187.1 U33.3(ISET)
N18115527: C143.1 R186.2 U33.4(EN)
N18245213: LED1.1(CATHODE) Q3.3(COLLECTOR)
N18245628: LED1.2(ANODE) R16.2
N18246356: Q3.1(BASE) R19.2 R21.1
N18288623: C61.1 D8.2 R43.1 R227.1 SW4.3(B1) SW4.4(B2)
N18355550: J11.3 R57.2
N18579208: D48.2 J33.2 R219.1
N18579211: D47.2 J33.3 R220.1
N18585387: D50.2 J32.2 R222.1
N18585389: D49.2 J32.3 R221.1
N18585721: D52.2 J34.2 R224.1
N18585723: D51.2 J34.3 R223.1
N18585912: D54.2 J35.2 R226.1
N18585914: D53.2 J35.3 R225.1

Not connected (* = marked no-connect by the designer): H1 1(NC)*; H2 1(NC)*; H3 1(NC)*; H4 1(NC)*; J9 1*; J23 13* 14*; J24 13* 14* 16* 17* 18* 19* 20* 21*; J25 1* 14* 24* 25* 30*; J27 3(MIC-N)* 5(SPK-P)* 6(NC1)* 16(RESERVED6)* 17(RESERVED5)* 19(WAKEUP-IN)* 28(UART-CTS)* 30(UART-DCD)* 32(WAKEUP-OUT)* 42(LED-WWAN)* 44(USIM-PRESENCE)* 45(RESERVED1)* 46(UART-DTR)* 47(RESERVED2)* 48(NC2)* 49(RESERVED3)* 51(RESERVED4)*; U12 1(NC1)* 2(NC2)*; U36 4(CD)* 6(VPP)*; U37 3*

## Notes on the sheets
sheet 12
- MIPI CSI 0 PORT
- MIPI CSI 1 PORT
- GPIO3_A2
- GPIO3_A7
- GPIO2_B0
- GPIO2_A7
- Channel Gating
- MIPI CSI Power
- Default:4Lane
- GPIO1_B1
- 1A限流
- GPIO3_D4
- 1A限流
sheet 13
- MINI PCIE POWER
- SIM CARD
- 3.3v 3A
- FB 0.765V
- GPIO0_D4
- MINI PCIE
- GPIO3_B5
sheet 14
- EarPhone PORT
- MIC PORT
- 耳机插入时HP_DET口为低电平
  耳机未插入时HP_DET口为高电平
- GPIO1_B2
- KLXES15AAA1 *3
- SPK PORT
sheet 15
- RTC
- GPIO3_A5
- GPIO3_A6
- RS232 PORT
- Bidirectional Device
- Bidirectional Device
- SD Card
- KLXES15AAA1 *8
sheet 16
- I2C PORT 0
- UART PORT 0
- KLXES15AAA1*2
- KLXES15AAA1*2
- I2C PORT 1
- UART PORT 1
- KLXES15AAA1*2
- KLXES15AAA1*2
sheet 17
- DC IN : 12V
- SYSTEM Power SW And OCP
- 2A限流
- VCC3VS_SYS
- 3.3v 3A
- 1A限流
- FB 0.765V
- EN:1.3V(TYP)
- UVLO:10.5V
- SYS Power LED
- CPU FAN
- VCC5V0_SYS
- 贴片功率电感
- 5.2V 3A
- FB 0.765V
- EN:1.3V(TYP)
- UVLO:10.5V
- VCC5V0_SYS_2
- 贴片功率电感
- 5.2V 3A
- FB 0.765V
- Fix Hole
sheet 18
- eDP1.3 PORT
- EDP TOUCH
- GPIO3_B0
- GPIO3_B6
- GPIO0_C7
- PWM0_M0
- EDP Power
- GPIO1_B0
- 1A限流
- 1.5A熔断
sheet 19
- NOR SPI FLASH
- 上电或复位后，短接过孔
  进入MaskRom模式
- Button
- DEBUG
- 短按开机   长按关机
- IR Receiver
- LED
- 用户LED
- GPIO0_C0
